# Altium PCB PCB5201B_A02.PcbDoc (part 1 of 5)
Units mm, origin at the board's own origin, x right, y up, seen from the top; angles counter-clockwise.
Board outline 115 x 60 mm, 6 copper layers (Top Layer, GND Layer 2, Signal Layer 3, Signal Layer 4, VCC Layer 5, Bottom Layer), stack 1.555 mm thick; 355 components, 250 nets, 1223 pads, 1070 vias.
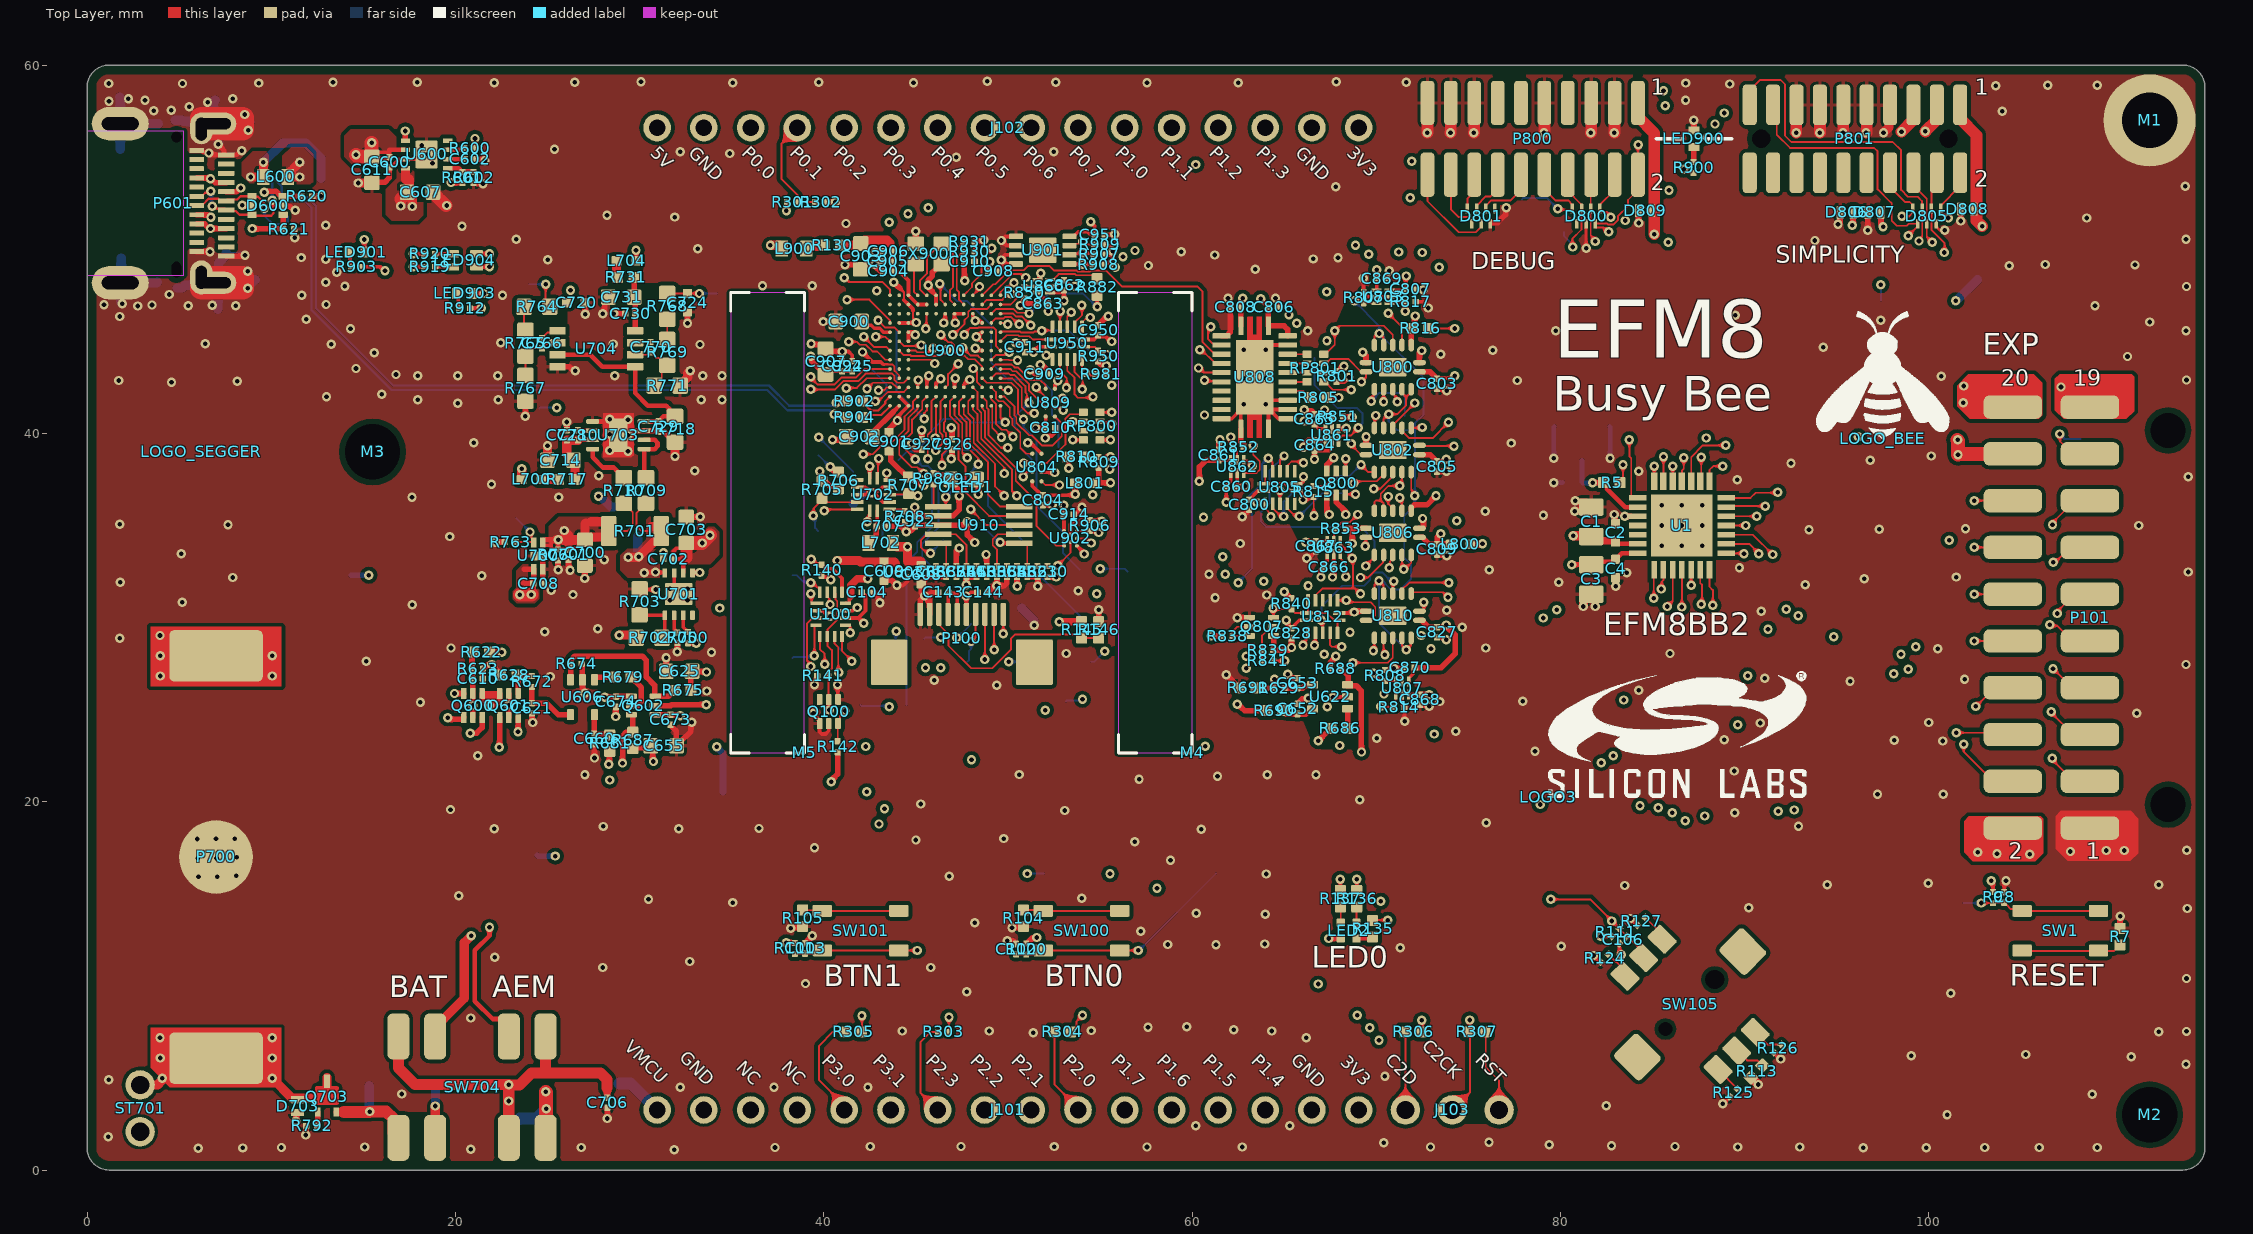
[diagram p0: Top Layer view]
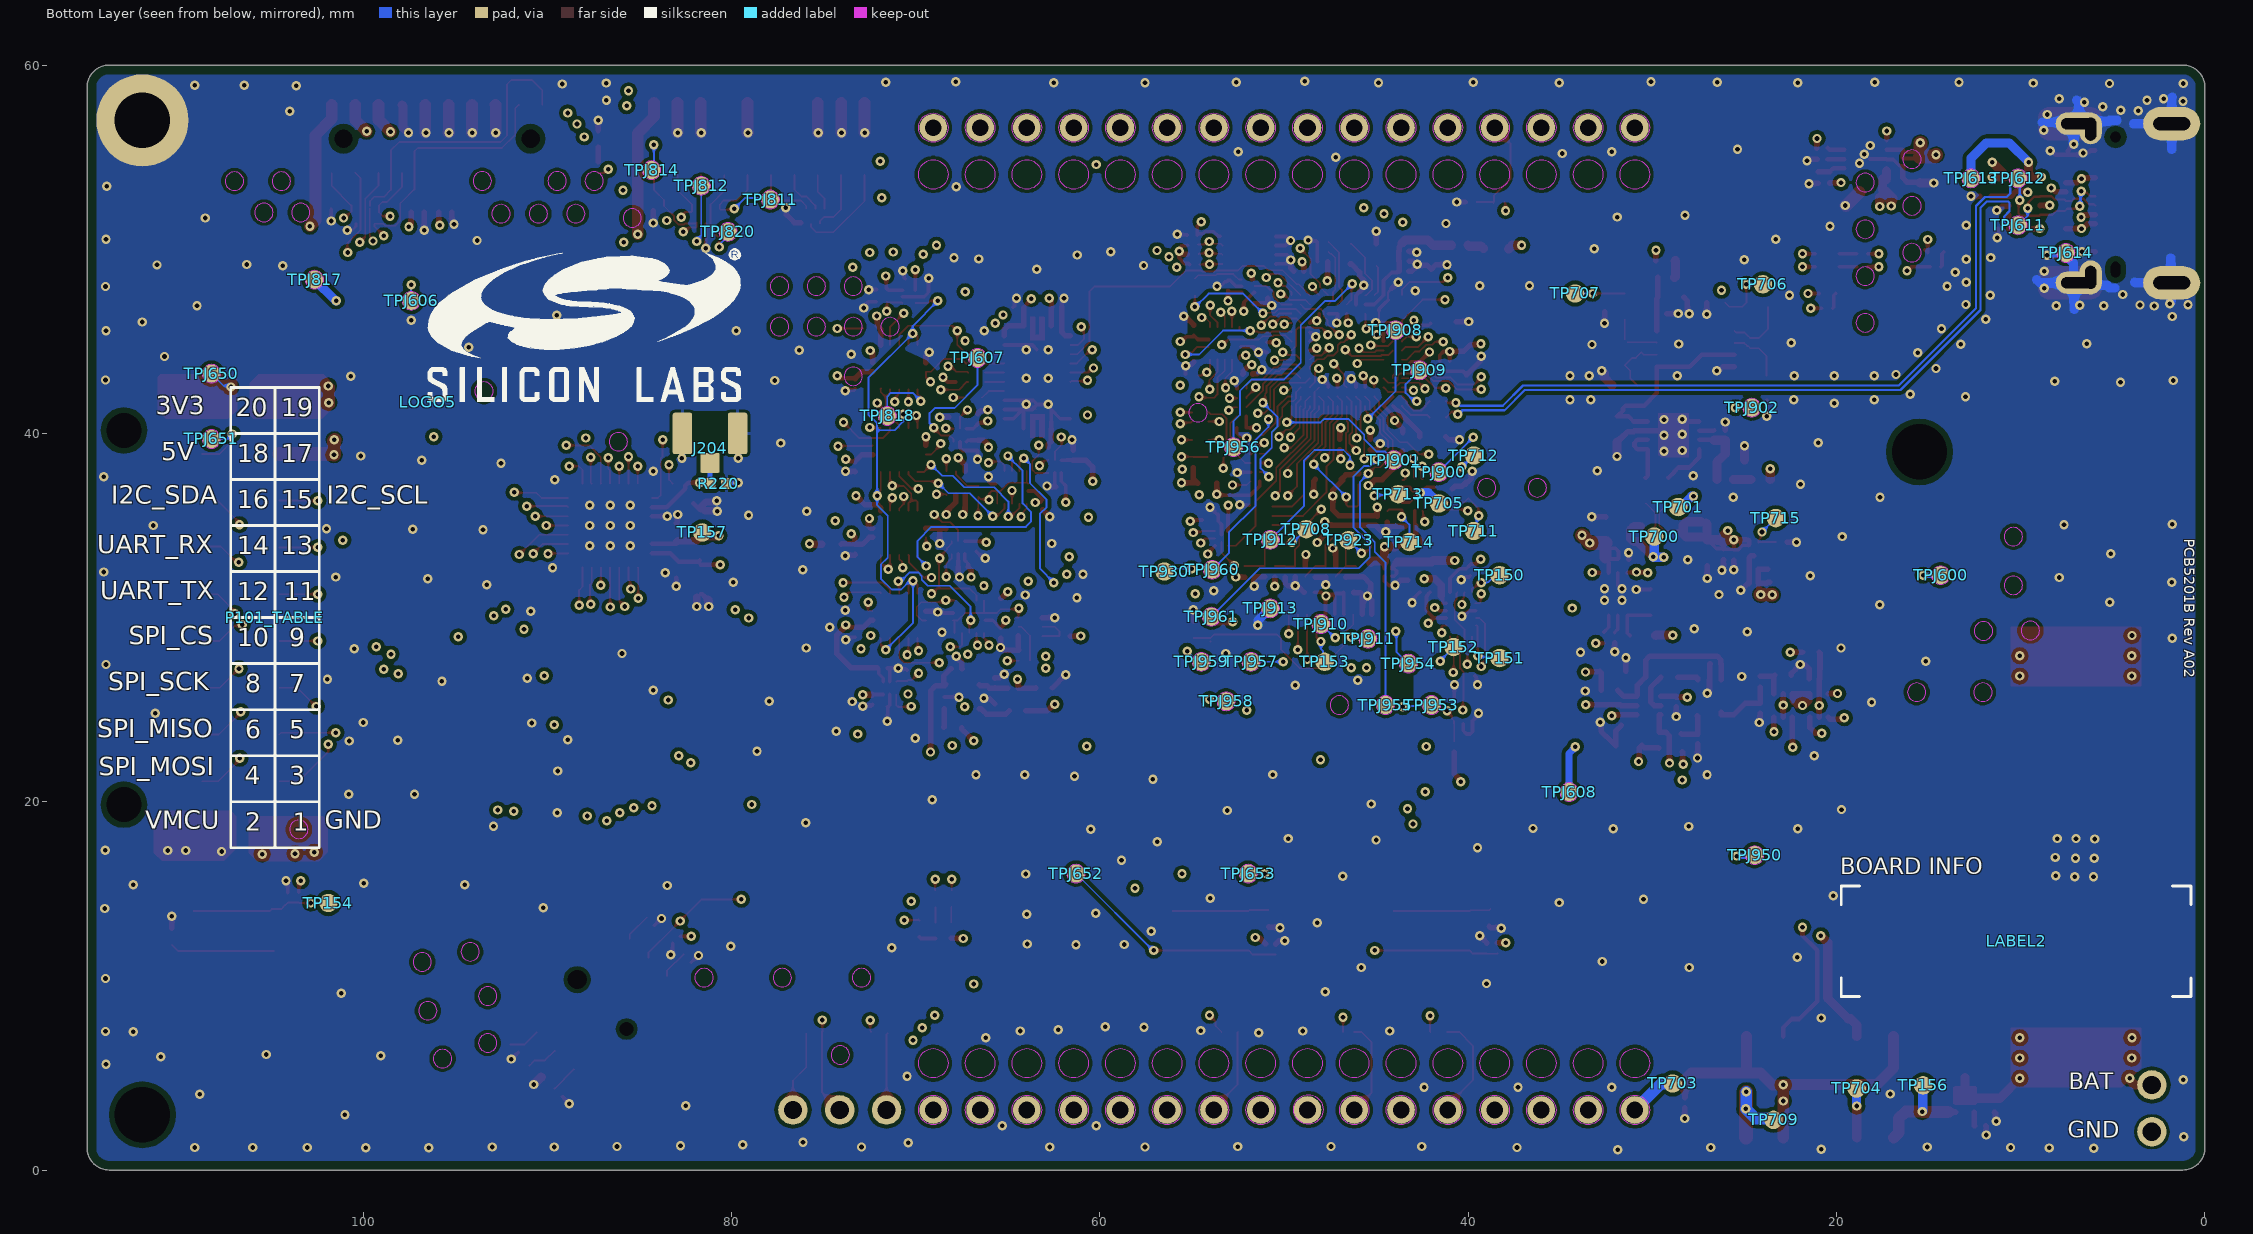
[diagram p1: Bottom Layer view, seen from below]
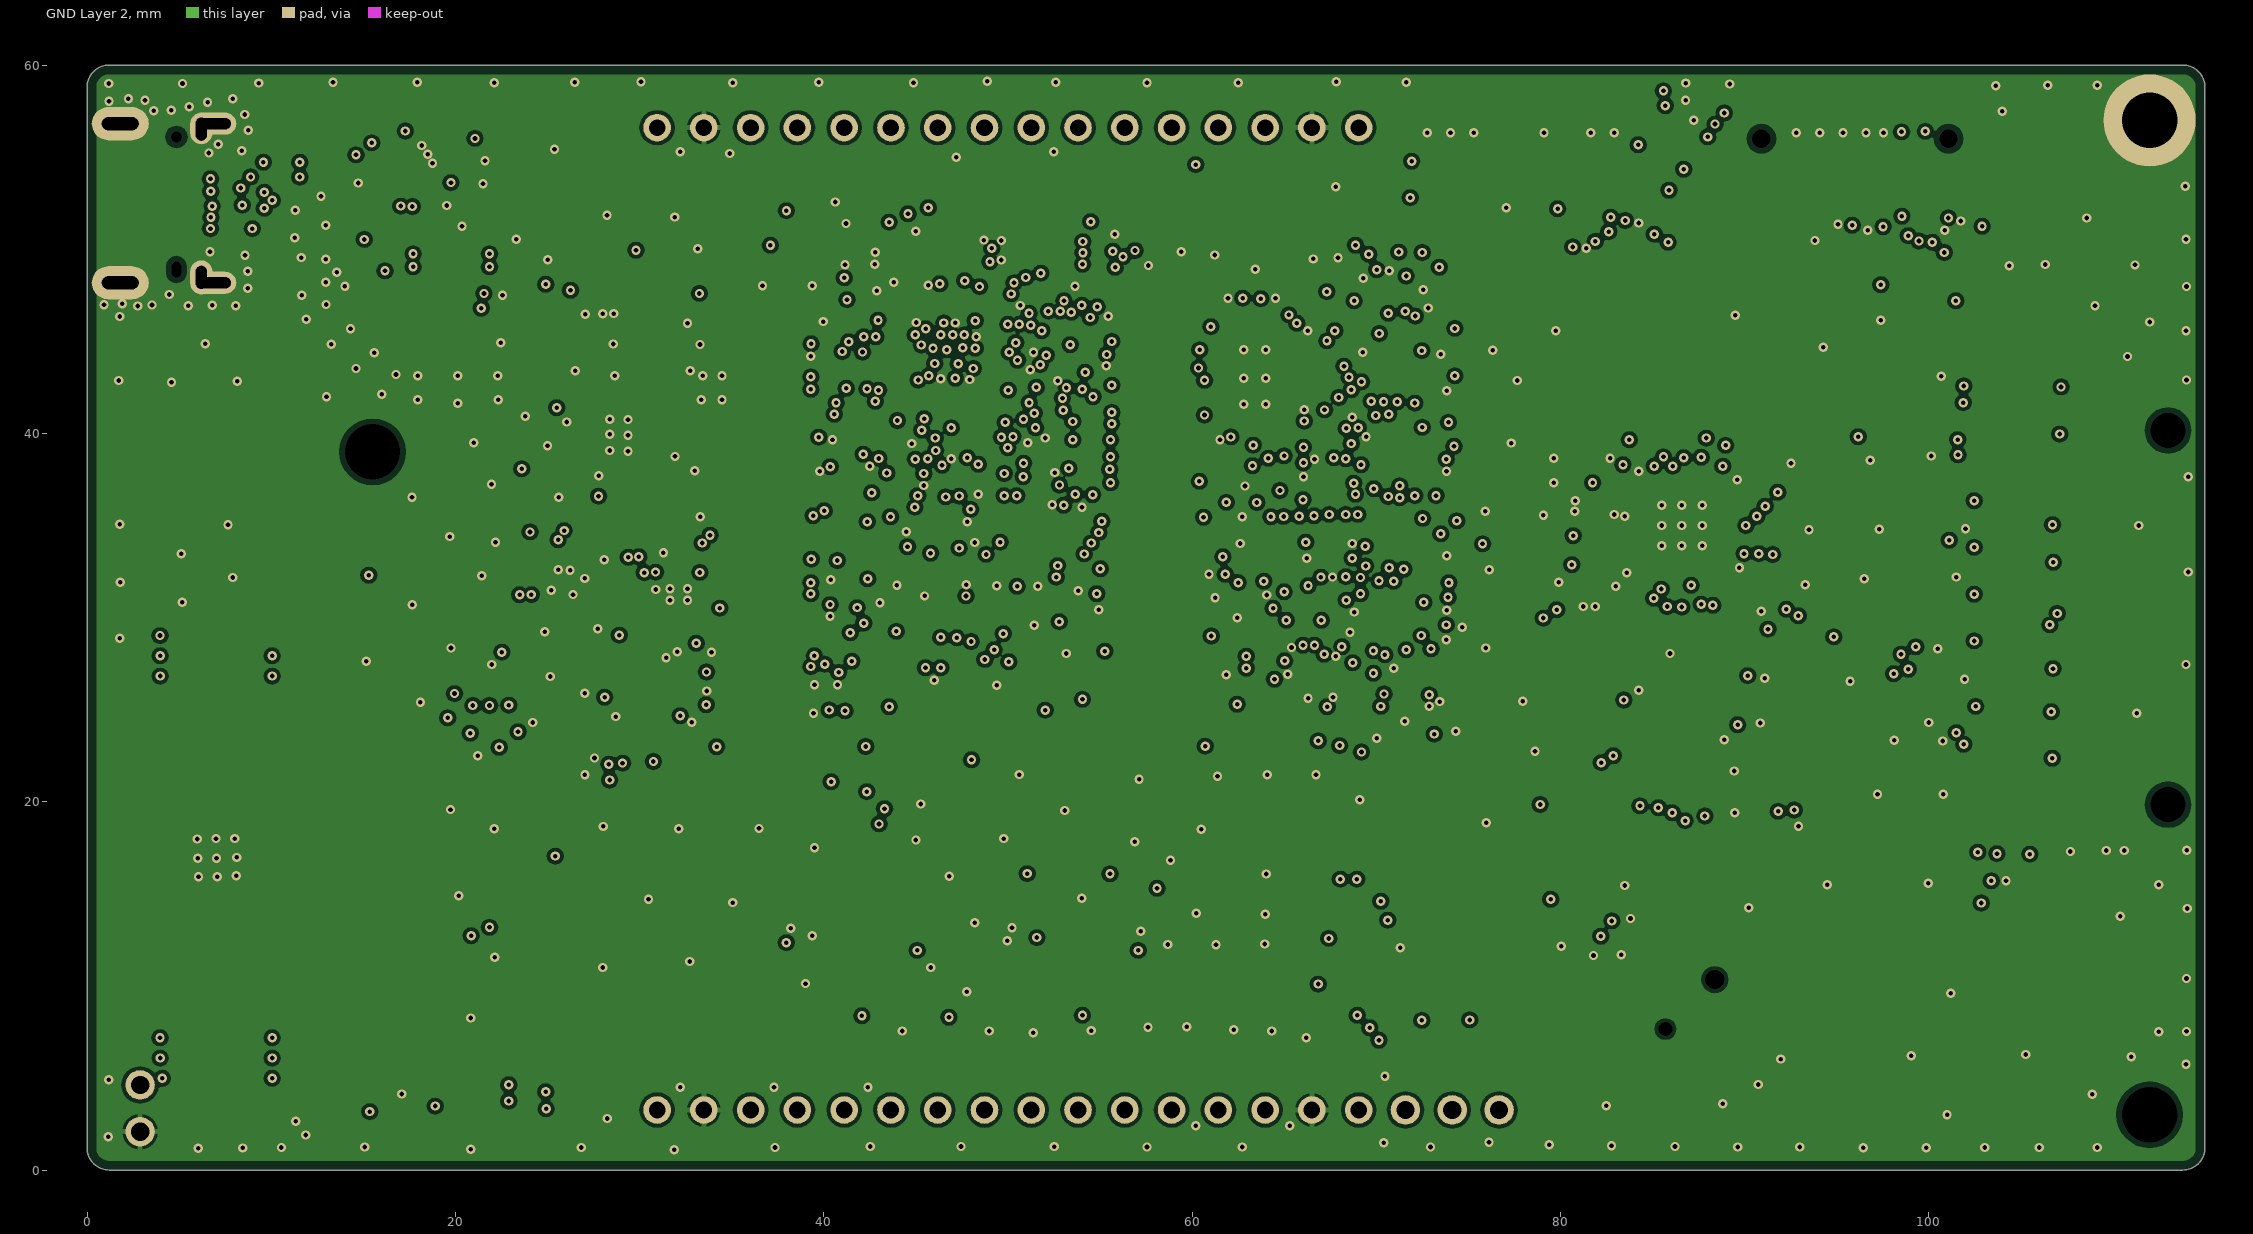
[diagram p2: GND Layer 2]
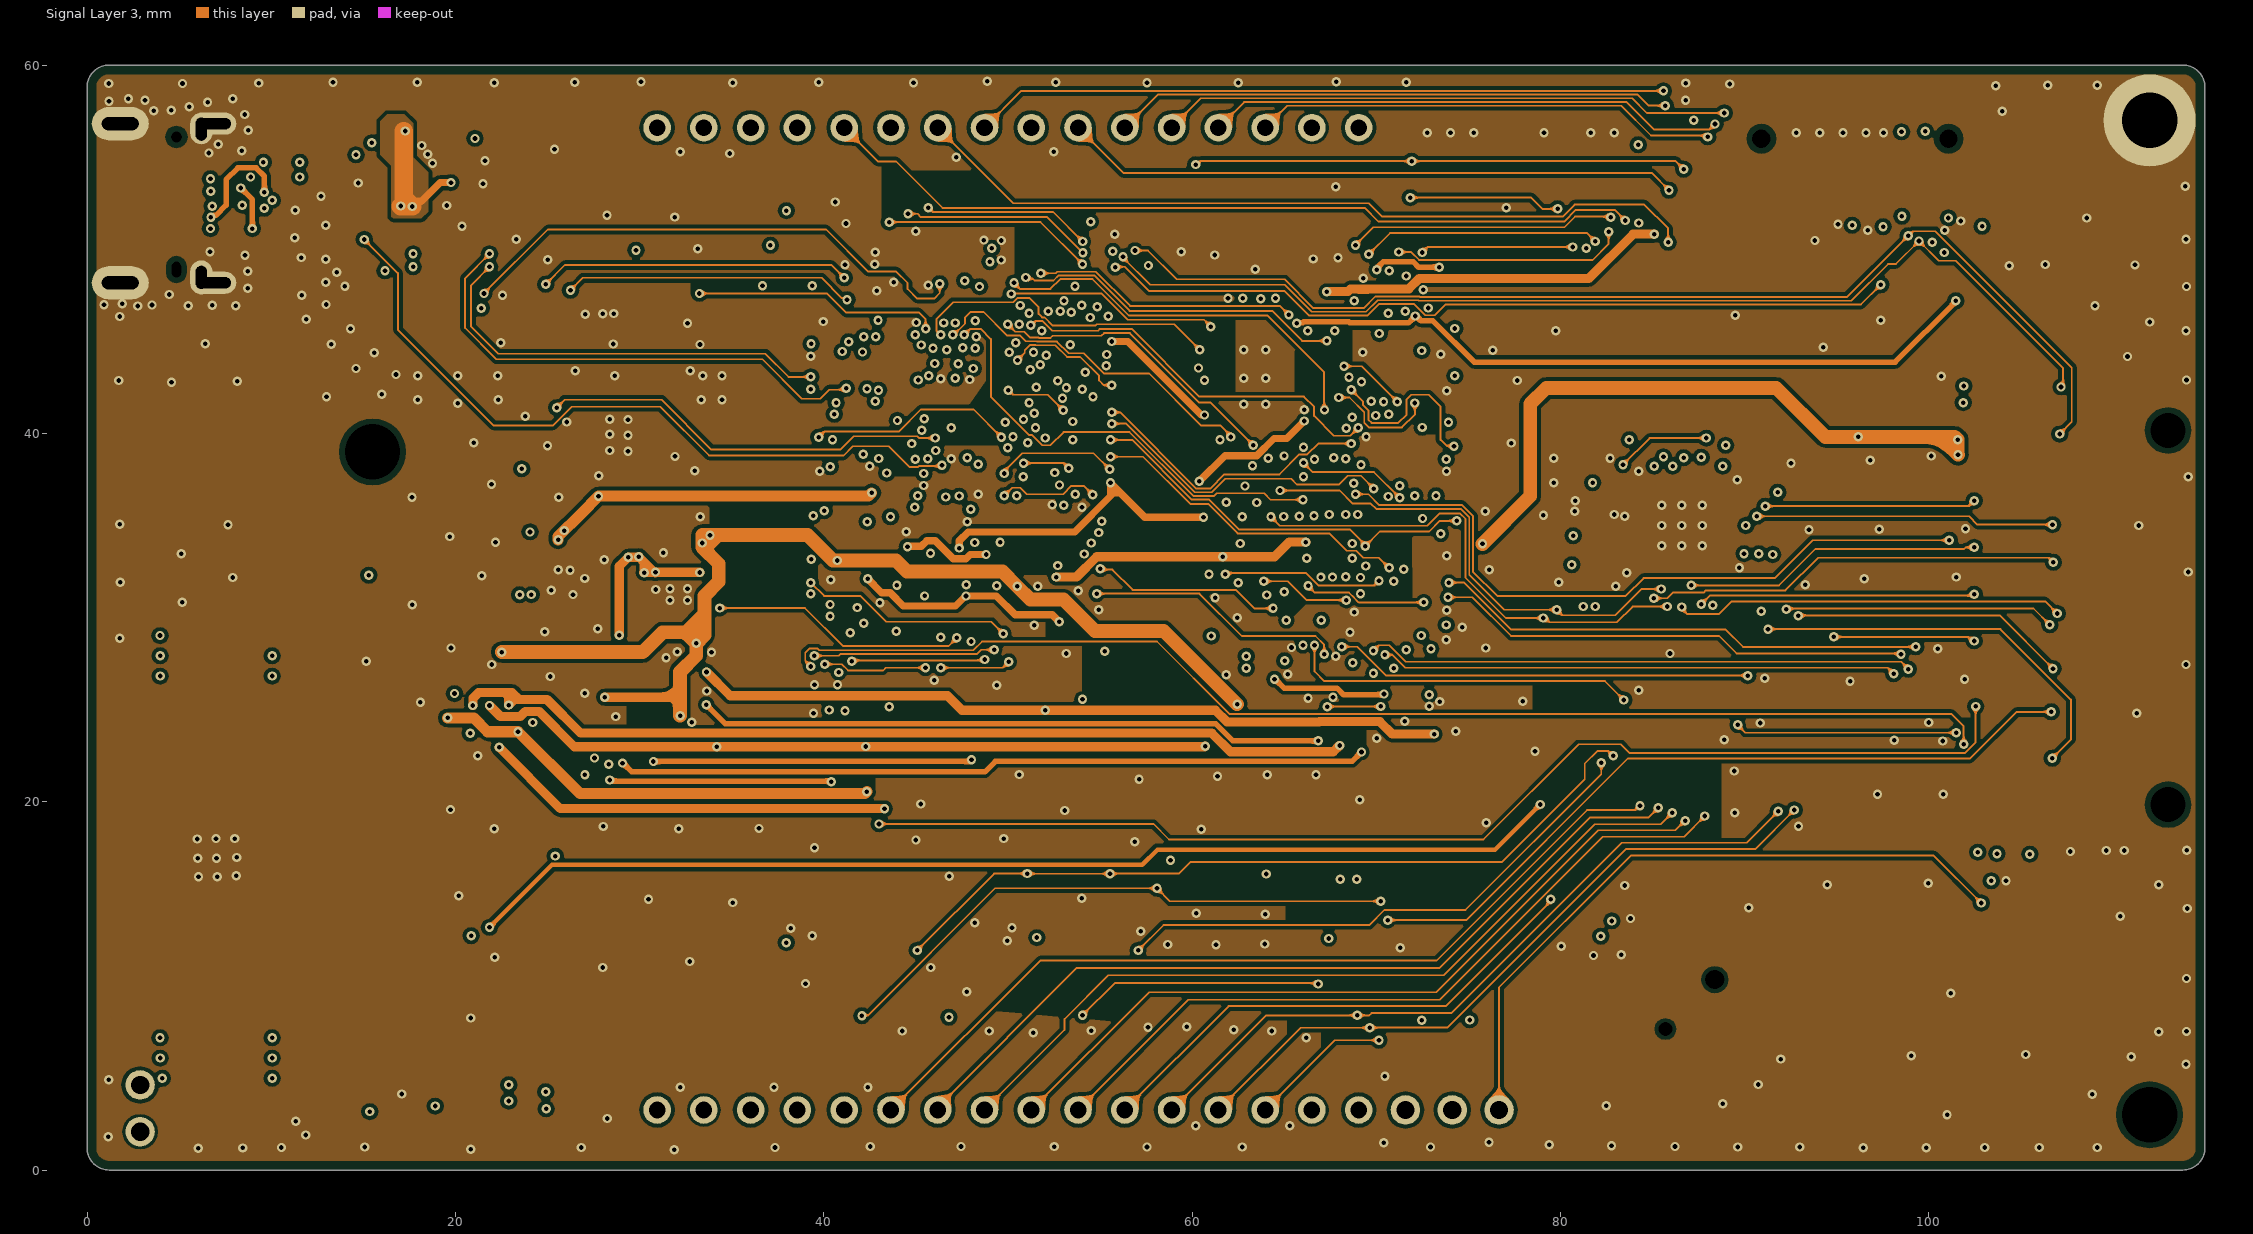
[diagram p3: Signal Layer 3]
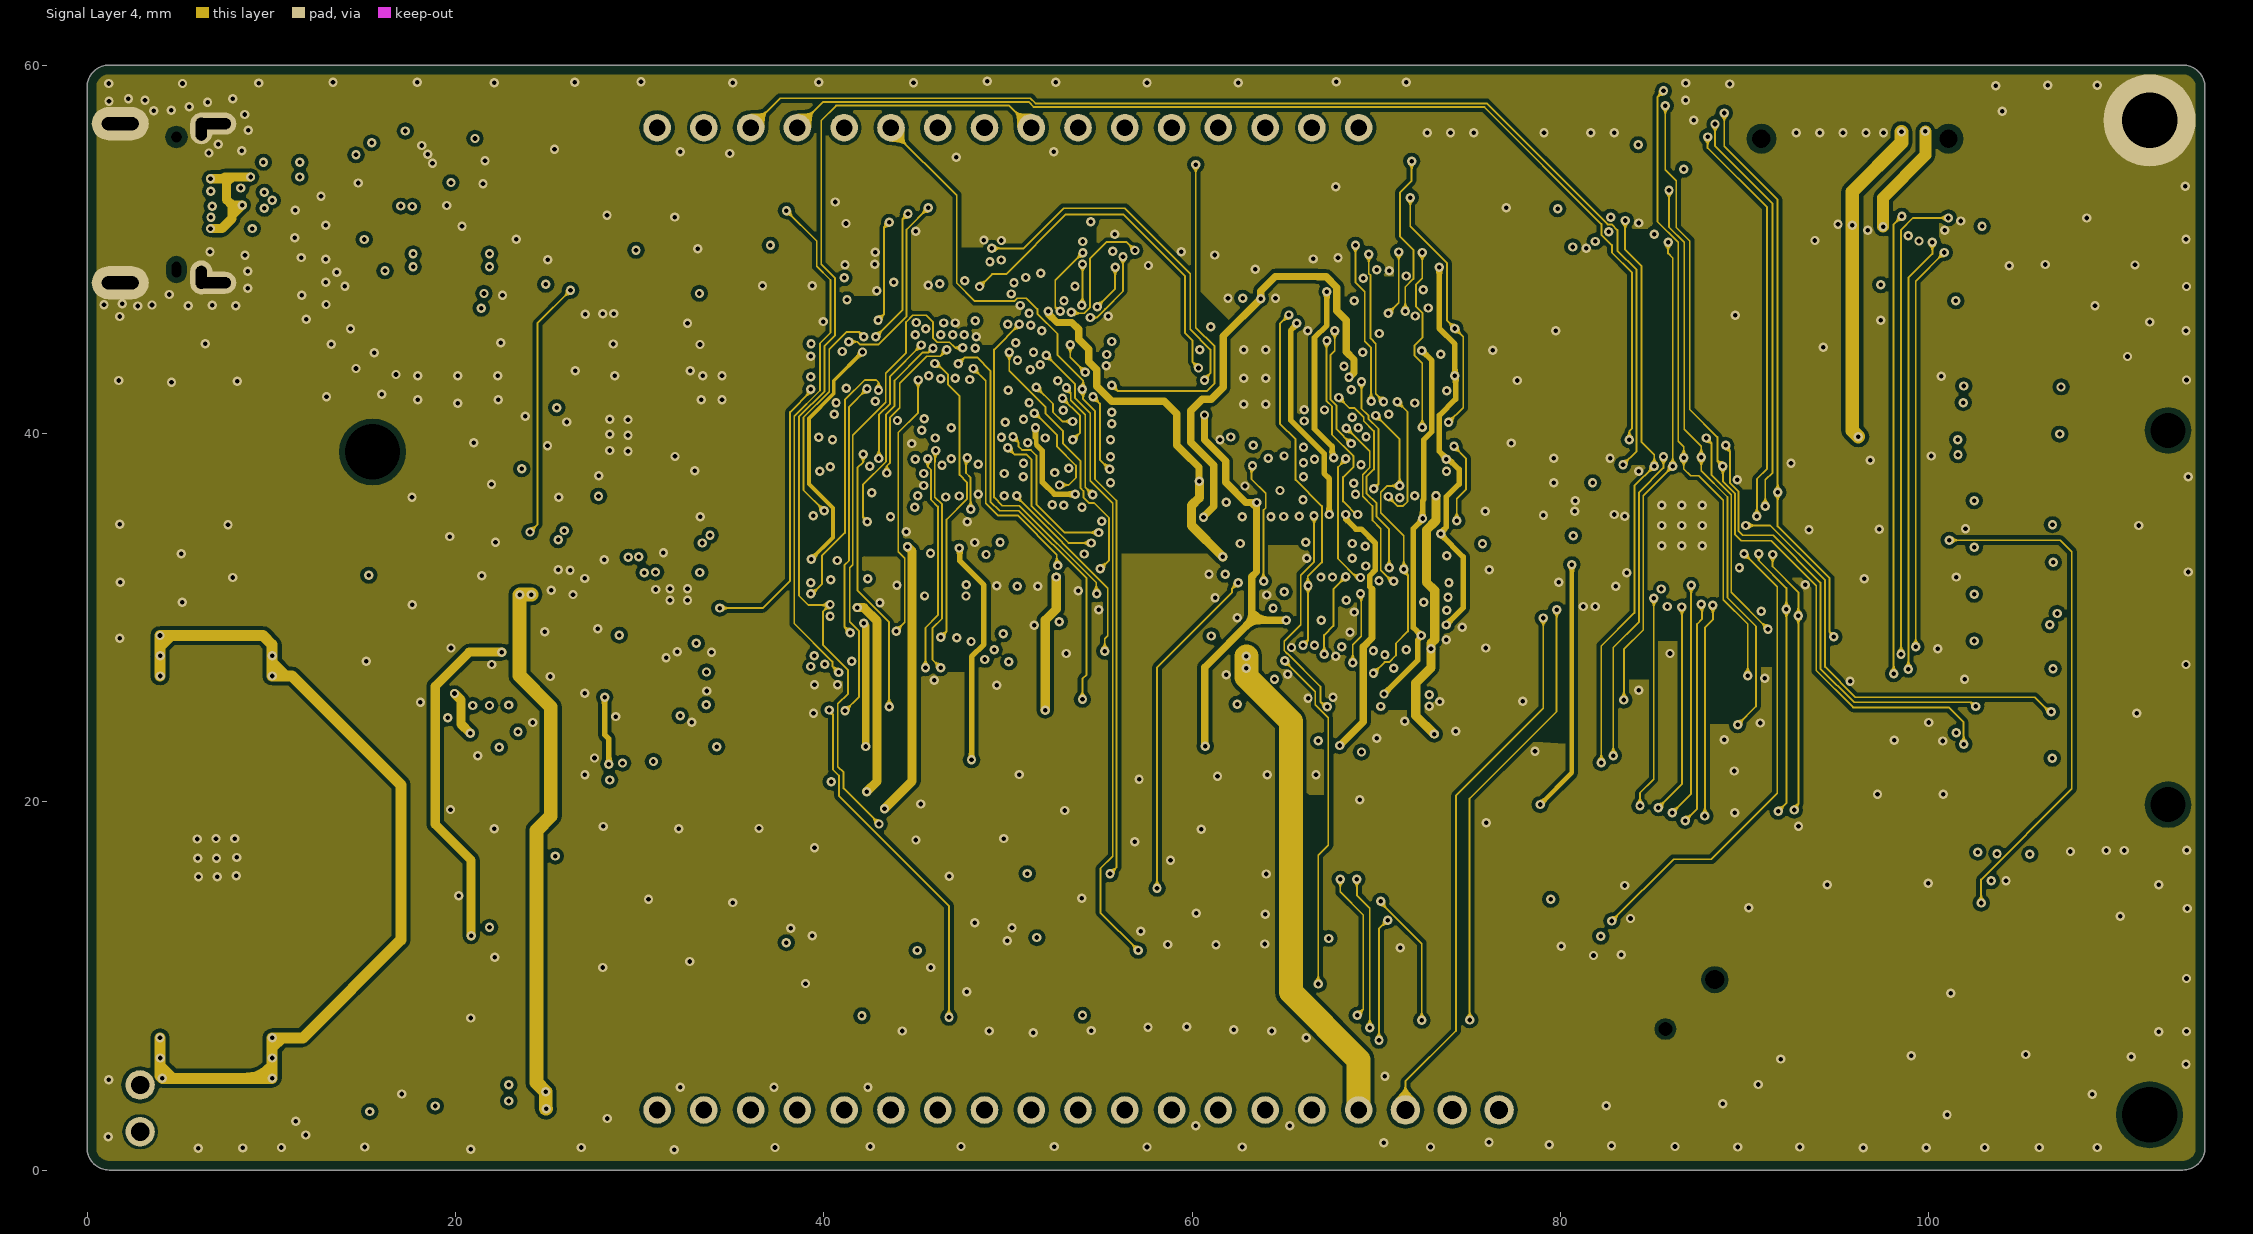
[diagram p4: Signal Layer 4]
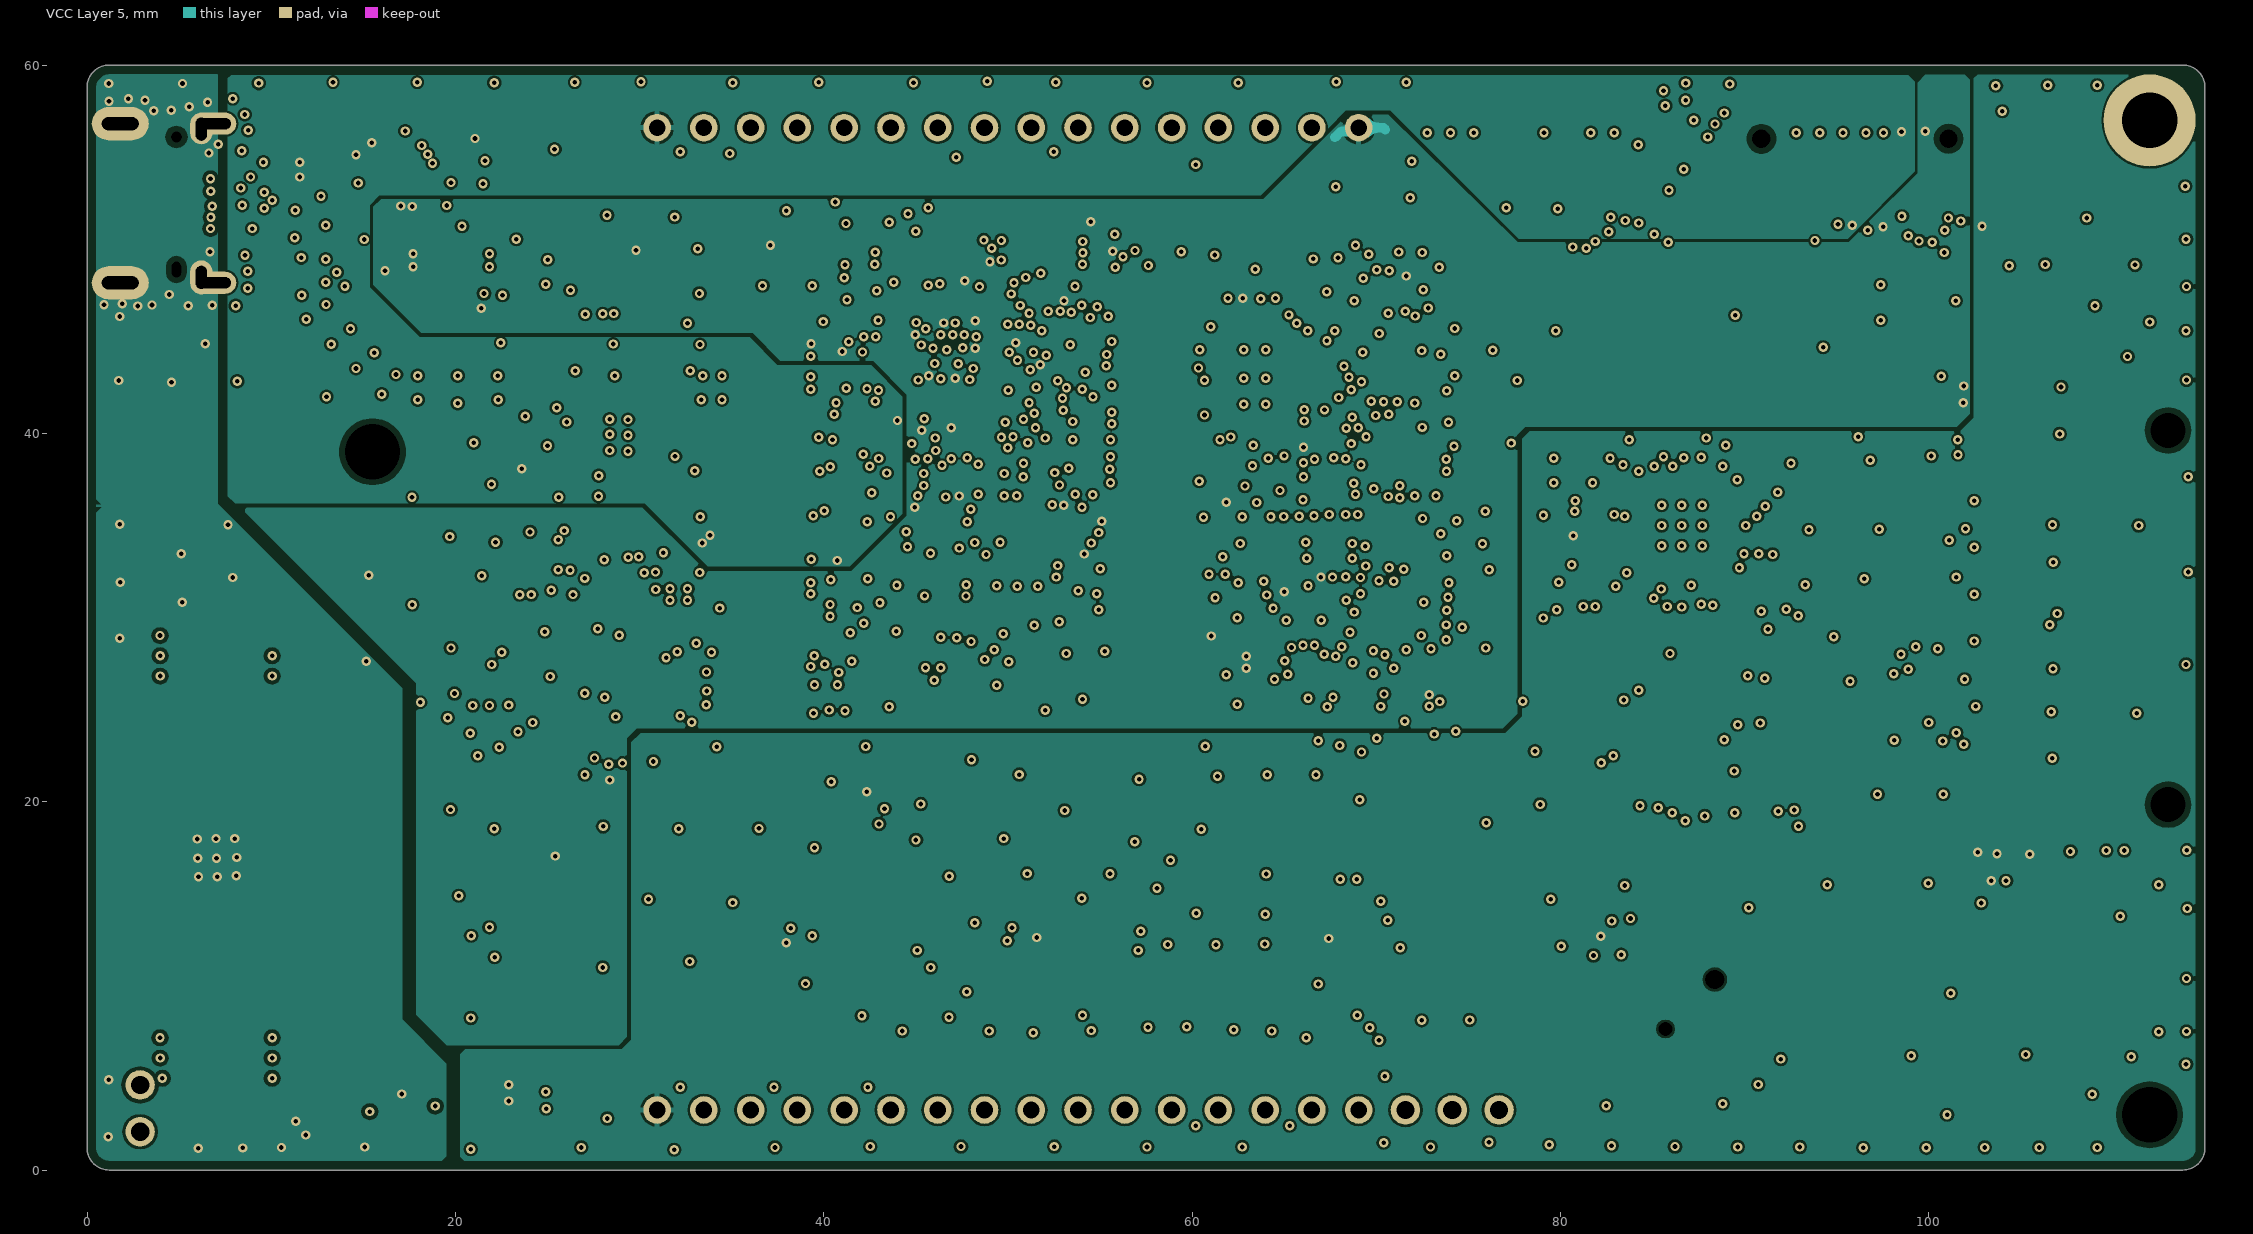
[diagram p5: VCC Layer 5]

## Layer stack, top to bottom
Top Solder: solder mask 0.03, Solder Resist, Dk 3.5
Top Layer: signal copper 0.035
Dielectric 1: prepreg 0.1, FR-4, Dk 4.2
GND Layer 2: signal copper 0.035
Dielectric 2: core 0.46, Core-009, Dk 4.2
Signal Layer 3: signal copper 0.035
Dielectric 3: prepreg 0.225, PP-006, Dk 4.2
Signal Layer 4: signal copper 0.035
Dielectric 4: core 0.46, Core-009, Dk 4.2
VCC Layer 5: signal copper 0.035
Dielectric  5: prepreg 0.1, FR-4, Dk 4.2
Bottom Layer: signal copper 0.035
Bottom Solder: solder mask 0.03, Solder Resist, Dk 3.5

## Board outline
0,1.2 0,58.8 cw(c1.2,58.8) 1.2,60 113.8,60 cw(c113.8,58.8) 115,58.8 115,1.2 cw(c113.8,1.2) 113.8,0 1.2,0 cw(c1.2,1.2)

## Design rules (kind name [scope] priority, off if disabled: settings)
BoardOutlineClearance BoardOutlineClearance_IGNORE_USB [HasFootprint('FCI_10137065_USB-C_RCPT_A1') or IsKeepOut] p1: gap=0.5 ignorepadtopadclearanceinfootprint=FALSE except(0: Region-OutlineEdge Region-CavityEdge Region-CutoutEdge Region-SplitBarrior Region-SplitContinuation; 0.25: THPad-OutlineEdge; 0.26: Arc-CutoutEdge Track-CutoutEdge SMDPad-CutoutEdge THPad-CutoutEdge Via-CutoutEdge Fill-CutoutEdge Poly-CutoutEdge Text-CutoutEdge)
BoardOutlineClearance [All] p2: gap=0.5 ignorepadtopadclearanceinfootprint=FALSE except(0.26: Arc-CutoutEdge Track-CutoutEdge SMDPad-CutoutEdge THPad-CutoutEdge Via-CutoutEdge Fill-CutoutEdge Poly-CutoutEdge Region-CutoutEdge Text-CutoutEdge; 0.4: THPad-OutlineEdge)
Clearance Clearance_NPL [(ObjectKind = 'Pad') And (Layer = 'MultiLayer') And (PadIsPlated = 'False')] p1: gap=0.3 ignorepadtopadclearanceinfootprint=FALSE
Clearance Clearance_Polygon_GND [InNet('GND') and InPolygon] p2: gap=0.2 ignorepadtopadclearanceinfootprint=FALSE
Clearance Clearance_Polygon_General [InPolygon] p3: gap=0.125 ignorepadtopadclearanceinfootprint=FALSE
Clearance Clearance_Via_Track [IsVia vs IsTrack] p4: gap=0.089 ignorepadtopadclearanceinfootprint=FALSE except(0: Arc-Hole Track-Hole SMDPad-Hole THPad-Hole Via-Hole Fill-Hole Poly-Hole Region-Hole Text-Hole)
Clearance [All] p5: gap=0.1 ignorepadtopadclearanceinfootprint=FALSE
Clearance Clearance_P601 [InComponent('P601')] p6: gap=0.1 ignorepadtopadclearanceinfootprint=FALSE
ComponentClearance ComponentClearance_IGNORE [HasFootprint('TESTJIGG_PCB4002_M14') OR HasFootprint('TAB50.5_T1.6_W2.4') OR HasFootprint('TP_6.0X6.0_MILLOUT_5.0X5.0_TH') Or InComponent('M1')] p1: gap=0 collisioncheckmode=3 verticalgap=0 showdistances=FALSE
ComponentClearance [All] p2: gap=0.2 collisioncheckmode=3 verticalgap=0.254 showdistances=FALSE
DiffPairsRouting DiffPairsRouting_90OHM [InDifferentialPair('USB_90') or InDifferentialPair('USB_90_U900')] p1: maxlimit=0.254 minlimit=0.12 mostfreqgap=0.254 toplayer_maxgap=0.12 toplayer_prefgap=0.12 toplayer_minwidth=0.12 toplayer_maxwidth=0.12 toplayer_prefwidth=0.12 bottomlayer_maxgap=0.12 bottomlayer_prefgap=0.12 bottomlayer_minwidth=0.12 bottomlayer_maxwidth=0.12 bottomlayer_prefwidth=0.12 impedanceprofiledriven=TRUE impedanceprofileid={B4300C99-598D-4438-91CE-854F904B181D} impedanceprofilevalue=90.000000 maxuncoupledlength=50
HoleSize [All] p1: absolutevalues=TRUE maxlimit=10 minlimit=0.1 maxpercent=80.000 minpercent=20.000
HoleToHoleClearance HoleToHoleClearance_general [Not InComponent('P601')] p1: gap=0.254 allowstackedmicrovias=TRUE
MinimumSolderMaskSliver MinimumSolderMaskSliver_IGNORE [InComponent('LOGO*') vs InComponent('LOGO*')] p1: minsoldermaskwidth=0
MinimumSolderMaskSliver [All] p2: minsoldermaskwidth=0.1
PolygonConnect PolygonConnect_Direct_Connect [InComponent('M1') or InComponent('J1') or InComponent('P700') or InComponent('P601')] p1: connectstyle=Direct reliefconductorwidth=0.33 reliefentries=4 polygonreliefangle="90 Angle" airgapwidth=0.152
PolygonConnect PolygonConnect_IGNORE_GND_FILL [IsThruPin vs InNet('GND') and not OnLayer('GND Layer 2')] p2: connectstyle=NoConnect reliefconductorwidth=0.3 reliefentries=4 polygonreliefangle="90 Angle" airgapwidth=0.15
PolygonConnect PolygonConnect_general [All] p3: thpad.connectstyle=Relief thpad.reliefconductorwidth=0.3 thpad.reliefentries=4 thpad.polygonreliefangle="90 Angle" thpad.airgapwidth=0.15 smdpad.connectstyle=Relief smdpad.reliefconductorwidth=0.2 smdpad.reliefentries=4 smdpad.polygonreliefangle="90 Angle" smdpad.airgapwidth=0.15 via.connectstyle=Direct via.reliefconductorwidth=0.33 via.reliefentries=4 via.polygonreliefangle="90 Angle" via.airgapwidth=0.127
RoutingVias RoutingVias_Through [InDrillLayerPair('Top Layer - Bottom Layer')] p1: holewidth=0.25 width=0.508 viastyle="Through Hole" minholewidth=0.25 minwidth=0.508 maxholewidth=1 maxwidth=1.5 useviatemplates=TRUE viatemplateguid#1={89E5EF08-91F7-4BC1-BF72-0CDB5ADAF91B} viatemplatename#1=v51h25m0mx0(Tol8-8)
ShortCircuit ShortCircuit_General [All] p1: allowed=FALSE
SilkToSilkClearance [All] p1: silktosilkclearance=0.102
SilkToSolderMaskClearance [IsPad] p1: minsilkscreentomaskgap=0.102 clearancetoexposedcopper=TRUE
SolderMaskExpansion [All] p1: expansion=0.05 istentingtop=FALSE
UnRoutedNet [All] p1: checkbadconnections=TRUE
Width [All] p1: maxlimit=5.08 minlimit=0.1 preferedwidth=0.1 minimp=50.000000 maximp=50.000000 favimp=50.000000
21 further rules are at their usual default settings.

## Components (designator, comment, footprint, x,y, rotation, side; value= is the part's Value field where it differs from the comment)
C1 "10U" C0805 81.675,35.2 r90 top
C2 "100N" C0402 83,34.6 r90 top
C3 "10U" C0805 81.675,32.069 r270 top
C4 "100N" C0402 83,32.662 r270 top
C8 "100N" C0201 104.1,14.8 r90 top
C102 "1N" C0201 50.45,12 r90 top
C103 "1N" C0201 38.986,12.031 r90 top
C104 "100N" C0201 42.348,31.374 r0 top
C106 "1N" C0201 83.4,12.5 r225 top
C143 "100N" C0201 46.499,31.364 r180 top
C144 "100N" C0201 48.625,31.368 r0 top
C600 "100N" C0201 16.417,54.726 r270 top
C602 "33N" C0201 20.782,54.897 r0 top
C607 "10U" C0603 18.082,53.097 r0 top
C608 "1U" C0402 45.3,32.325 r270 top
C609 "1U" C0402 43.275,32.525 r270 top
C610 "1N" C0201 21.2,26.675 r0 top
C611 "10U" C0603 15.465,54.314 r270 top
C621 "100N" C0201 24.15,25.075 r270 top
C625 "10U" C0603 32.148,27.08 r180 top
C632 "10N" C0201 51.05,32.5 r270 top
C635 "10N" C0201 49.4,32.5 r270 top
C638 "10N" C0201 46.1,32.5 r270 top
C641 "10N" C0201 47.75,32.5 r270 top
C652 "100N" C0201 65.725,25.036 r90 top
C653 "100N" C0201 65.72,26.44 r90 top
C655 "10U" C0603 31.304,23.036 r0 top
C660 "100N" C0201 27.537,23.41 r270 top
C673 "100N" C0201 31.675,24.45 r270 top
C674 "100N" C0201 28.713,25.422 r270 top
C700 "10U" C0603 27.033,33.525 r270 top
C701 "100N" C0201 26.134,33.412 r270 top
C702 "100N" C0201 31.57,33.171 r180 top
C703 "10U" C0603 32.535,34.761 r90 top
C705 "33N" C0201 32.05,28.904 r270 top
C706 "100N" C0201 28.25,3.65 r270 top
C707 "100N" C0201 43.15,34.95 r0 top
C708 "100N" C0201 24.5,31.85 r0 top
C710 "100N" C0201 26.65,39.9 r90 top
C714 "10U" C0603 25.7,38.55 r180 top
C720 "1N" C0402 26.55,47.1 r0 top
C724 "1N" C0402 32.6,47.1 r270 top
C728 "100N" C0201 26.05,39.9 r90 top
C729 "2N2" C0201 31.025,40.375 r270 top
C730 "100N" C0201 29.497,46.509 r180 top
C731 "10U" C0603 29,47.4 r180 top
C766 "10P" C0201 24.7,44.9 r90 top
C770 "10P" C0201 30.6,44.675 r90 top
C800 "100N" C0201 63.1,36.125 r270 top
C803 "100N" C0201 73.3,42.7 r270 top
C804 "100N" C0201 51.9,36.375 r270 top
C805 "100N" C0201 73.3,38.2 r270 top
C806 "100N" C0201 64.45,46.85 r0 top
C807 "100N" C0201 71.85,47.825 r0 top
C808 "100N" C0201 62.35,46.85 r180 top
C809 "100N" C0201 73.3,33.7 r270 top
C810 "100N" C0201 52.3,40.3 r0 top
C827 "100N" C0201 73.3,29.2 r270 top
C828 "100N" C0201 65.4,29.15 r270 top
C860 "100N" C0201 62.125,37.1 r0 top
C861 "100N" C0201 61.45,38.825 r90 top
C862 "100N" C0201 53.05,48.05 r90 top
C863 "100N" C0201 51.9,47.05 r180 top
C864 "100N" C0201 66.65,39.35 r270 top
C865 "100N" C0201 66.65,40.775 r90 top
C866 "100N" C0201 67.425,32.725 r0 top
C867 "100N" C0201 66.725,33.875 r270 top
C868 "100N" C0201 72.376,25.539 r270 top
C869 "100N" C0201 70.294,48.403 r0 top
C870 "100N" C0201 71.814,27.284 r180 top
C900 "1U" C0603 41.35,46.075 r180 top
C901 "1U" C0402 43.55,39.55 r270 top
C902 "4U7" C0603 41.925,39.825 r180 top
C903 "10U" C0603 42.006,49.615 r270 top
C904 "10N" C0201 43.498,48.802 r180 top
C905 "10N" C0201 43.485,49.352 r180 top
C906 "10N" C0201 43.498,49.896 r180 top
C907 "4U7" C0603 40.1,43.9 r270 top
C908 "100N" C0201 49.2,48.8 r0 top
C909 "100N" C0201 51.98,43.224 r180 top
C910 "100N" C0201 47.909,49.333 r0 top
C911 "100N" C0201 50.925,44.675 r270 top
C914 "100N" C0201 53.3,35.6 r0 top
C921 "4U7" C0603 47.6,37.5 r0 top
C922 "100N" C0201 44.95,35.225 r270 top
C924 "100N" C0201 41,43.65 r270 top
C925 "100N" C0201 41.55,43.65 r270 top
C926 "100N" C0201 46.975,39.4 r270 top
C927 "100N" C0201 45.325,39.4 r270 top
C950 "10N" C0201 54.9,45.6 r90 top
C951 "100N" C0201 54.997,50.778 r0 top
D600 "DT1446-04" SOT563_DIODES 9.797,52.374 r180 top
D703 "ESD" X2-DFN1006-2 11.425,3.475 r270 top
D800 "PUSB3AB6" DFN2111-7_M050_1.2X2.1_NXP 81.4,51.8 r270 top
D801 "PUSB3AB6" DFN2111-7_M050_1.2X2.1_NXP 75.7,51.8 r270 top
D805 "PUSB3AB6" DFN2111-7_M050_1.2X2.1_NXP 99.9,51.8 r270 top
D806 "ESD" X2-DFN1006-2 95.55,52 r180 top
D807 "ESD" X2-DFN1006-2 97.05,52 r180 top
D808 "ESD" X2-DFN1006-2 102.098,52.181 r180 top
D809 "ESD" X2-DFN1006-2 84.6,52.1 r180 top
J101 "1X16 2.54MM" HDR_M254-1X16_NO_3D 30.95,3.262 r0 top locked
J102 "1X16 2.54MM" HDR_M254-1X16_NO_3D 30.95,56.602 r0 top locked
J103 "1X3 2.54MM" HDR_M254-1X3_NO_3D 71.59,3.262 r0 top
J204 "U.FL" HRS_U.FL-R-SMT 81.175,40 r180 bottom
L600 "742792662" COIL_WURTH_CBF_0603 10.235,53.926 r0 top
L700 "742792796" COIL_0402 24.125,37.5 r0 top
L702 "74279266" COIL_WURTH_CBF_0603 43.1,34.05 r180 top
L704 "742792796" COIL_0402 29.282,49.375 r180 top
L800 "742792796" COIL_0402 74.574,33.978 r180 top
L801 "742792796" COIL_0402 54.175,37.3 r180 top
L900 "74279266" COIL_WURTH_CBF_0603 38.39,50.035 r0 top
LABEL2 "Comment" LABEL_4CORNERS_19.0X6.0 10.25,12.425 r180 bottom
LED2 "RGB" LED_LUMEX_SML-LX0404-4 68.5,13 r0 top
LED900 "YELLOW" LED_0402_CAT2 87.25,56 r90 top
LED901 "BLUE" LED_0402_CAT2 14.625,49.85 r0 top
LED903 "RED" LED_0402 20.5,47.6 r180 top
LED904 "LED_G_R" LED_AVAGO_HSMF-C165-4 20.5,49.4 r0 top
LOGO3 "Comment" LOGO_SILABS_W14.0_SILK 79.35,20.25 r0 top
LOGO5 "Comment" LOGO_SILABS_W18.0 96.5,41.7 r180 bottom
LOGO_BEE "Comment" LOGO_BEE_H7.0 97.5,39.7 r0 top
LOGO_SEGGER "Comment" LOGO_SEGGER_10.0X5.0_SM 6.2,39 r0 top
M1 "HOLE_PTH_3MM" HOLE_3.0_5.0_PL 112,57 r0 top
M2 "Comment" HOLE_3.0_NPL 112,3 r0 top
M3 "Comment" HOLE_3.0_NPL 15.5,39 r90 top
M4 "Comment" ADHESIVE_PAD_25.0X4.0 60,22.65 r90 top
M5 "Comment" ADHESIVE_PAD_25.0X4.0 38.95,22.65 r90 top
OLED1 "Comment" OLED_LS013B7DH03 47.725,37.075 r0 top
P100 "L-KLS1-242D-1.2-10" KLS_KLS1-242D_FPC_0.5-10 45.25,30.175 r0 top
P101 "HEADER_2X10_2.54MM_TH" WCON_1125B-1210_HOR_PEG-2X10 113,19.84 r90 top
P101_TABLE "Comment" LABEL_P101_PIN_TABLE_SL 104.8,30 r180 bottom
P601 "AMPH_10137065" FCI_10137065_USB-C_RCPT_A1 4.85,52.5 r270 top
P700 "CR2032" BAT_HOLD_MPD_BK-912_CR2032 7,17 r270 top
P800 "HEADER_DEBUG_ETM" WCON_3132_HDR_M127_SMD-2X10 78.5,56 r180 top
P801 "HEADER_2X10_1.27MM_SMD" HDR_SULLINS_M127_PEG-2X10 101.08,56 r180 top
Q100 "DMN5L06VK" SOT563 40.275,24.89 r270 top
Q600 "BSS84" SOT563 20.95,25.225 r90 top
Q601 "DMN5L06VK" SOT563 22.9,25.225 r90 top
Q602 "BSS84" SOT563 30.2,25.225 r0 top
Q703 "DMG3415" X2-DFN2015-3_DIODES 13.025,4.05 r90 top
Q800 "DMN5L06VK" SOT563 67.825,37.3 r270 top
Q807 "DMN5L06VK" SOT563 63.775,29.5 r180 top
R5 "0R" R0402 82.8,37.325 r0 top
R7 "100R" R0402 110.4,12.675 r270 top
R9 "1K" R0201 103.5,14.8 r270 top
R100 "1M" R0201 51,12 r90 top
R101 "1M" R0201 38.429,12.033 r90 top
R104 "100R" R0402 50.847,13.67 r270 top
R105 "100R" R0402 38.85,13.675 r270 top
R111 "10K" R0201 83,12.9 r225 top
R113 "100R" R0402 90.66,5.355 r45 top
R124 "15K" R0201 82.4,11.5 r45 top
R125 "10K" R0201 89.4,4.2 r45 top
R126 "33K" R0201 91.8,6.6 r45 top
R127 "60K4" R0201 84.4,13.5 r45 top
R130 "1R" R0402 40.454,50.219 r0 top
R135 "698R" R0402 69.8,13.1 r90 top
R136 "910R" R0402 68.944,14.734 r90 top
R137 "2K32" R0402 68.052,14.737 r90 top
R140 "100K" R0201 39.888,32.575 r90 top
R141 "10M" R0201 39.942,26.832 r0 top
R142 "100K" R0201 40.756,22.983 r270 top
R145 "0R" R0402 54.007,29.332 r90 top
R146 "0R" R0402 54.932,29.332 r270 top
R220 "49R9" R0402 80.725,37.275 r0 bottom
R301 "0R" R0201 38.3,52.564 r0 top
R302 "0R" R0201 39.846,52.564 r180 top
R303 "0R" R0201 46.5,7.5 r180 top
R304 "0R" R0402 52.95,7.5 r180 top
R305 "1K" R0402 41.6,7.5 r180 top
R306 "1K" R0402 72,7.5 r180 top
R307 "1K" R0402 75.47,7.5 r180 top
R600 "10K" R0201 20.782,55.497 r0 top
R601 "180K" R0201 20.382,53.897 r270 top
R602 "110K" R0201 20.982,53.897 r90 top
R620 "5K1" R0201 11.924,52.88 r180 top
R621 "5K1" R0201 10.95,51.1 r180 top
R622 "47R" R0402 21.4,28.125 r0 top
R623 "10K" R0201 21.2,27.225 r180 top
R628 "1M" R0402 22.9,26.875 r180 top
R629 "1K" R0201 64.719,26.163 r180 top
R630 "4K7" R0201 52.15,32.5 r270 top
R631 "10K" R0201 51.6,32.5 r90 top
R633 "47K" R0201 50.5,32.5 r270 top
R634 "47K" R0201 49.95,32.5 r90 top
R636 "47K" R0201 47.2,32.5 r90 top
R637 "47K" R0201 46.65,32.5 r90 top
R639 "47K" R0201 48.85,32.5 r90 top
R640 "47K" R0201 48.3,32.5 r90 top
R672 "1K" R0201 24.15,26.525 r90 top
R674 "4K7" R0201 26.56,27.49 r0 top
R675 "3R3" R0402 32.332,26.05 r0 top
R679 "0R" R0402 29.085,26.761 r0 top
R681 "33R" R0402 28.38,23.172 r270 top
R686 "0R" R0402 68.008,23.984 r180 top
R687 "3R3" R0402 29.629,23.333 r270 top
R688 "4K7" R0201 67.786,27.233 r180 top
R690 "33R" R0402 64.471,24.944 r180 top
R691 "1M" R0402 63.027,26.187 r180 top
R700 "10K" R0201 32.627,28.911 r270 top
R701 "4R7" R1206 29.75,34.7 r180 top
R702 "180K" R0603 30.516,28.9 r180 top
R703 "110K" R0603 30,30.856 r270 top
R705 "267R" R0402 39.9,36.929 r270 top
R706 "10K2" R0402 40.8,37.444 r90 top
R707 "24K9" R0402 44.6,37.189 r270 top
R708 "1M" R0201 44.4,35.475 r90 top
R709 "1K8" R0603 30.35,36.9 r270 top
R710 "1K8" R0603 29.15,36.9 r270 top
R717 "10R" R0402 26.05,37.5 r0 top
R718 "12K" R0603 31.925,40.225 r90 top
R731 "1R" R0402 29.25,48.475 r180 top
R760 "330K" R0201 25.573,33.403 r90 top
R763 "100K" R0201 22.979,34.098 r0 top
R764 "90R9" R0603 24.425,46.875 r0 top
R765 "51K" R0603 23.8,44.9 r90 top
R767 "160R" R0603 23.8,42.45 r90 top
R768 "90R9" R0603 31.5,46.9 r90 top
R769 "51K" R0603 31.5,44.4 r90 top
R771 "51K" R0603 31.5,42.6 r180 top
R792 "1K" R0201 12.2,2.4 r0 top
R801 "47K" R0201 67.849,43.093 r270 top
R805 "33R" R0402 66.85,41.95 r0 top
R807 "100K" R0201 69.325,47.375 r90 top
R808 "100K" R0201 70.475,26.85 r90 top
R809 "100K" R0201 54.925,38.425 r270 top
R810 "33R" R0402 53.7,38.725 r0 top
R814 "100K" R0201 71.232,25.13 r180 top
R815 "1K" R0201 66.59,36.842 r270 top
R816 "100K" R0402 72.4,45.7 r180 top
R817 "100K" R0201 71.85,47.15 r180 top
R838 "100K" R0201 61.901,28.996 r180 top
R839 "10M" R0201 64.1,28.225 r180 top
R840 "100K" R0201 65.4,30.75 r90 top
R841 "1K" R0201 64.104,27.652 r0 top
R850 "100K" R0201 50.9,47.642 r90 top
R851 "100K" R0201 67.9,40.912 r180 top
R852 "100K" R0201 62.5,39.25 r180 top
R853 "100K" R0201 68.075,34.825 r180 top
R882 "220R" R0402 54.85,47.95 r270 top
R900 "2K05" R0201 87.235,54.44 r90 top
R902 "33R" R0402 41.65,41.75 r0 top
R903 "5K76" R0201 14.625,49.05 r180 top
R904 "33R" R0402 41.65,40.875 r0 top
R906 "10K" R0201 54.45,35 r90 top
R907 "4K7" R0201 54.965,49.726 r180 top
R908 "4K7" R0201 54.898,49.168 r180 top
R909 "10K" R0201 54.976,50.251 r180 top
R912 "2K15" R0201 20.5,46.8 r180 top
R919 "1K" R0201 18.6,49.05 r0 top
R920 "2K37" R0201 18.6,49.75 r0 top
R930 "1K" R0201 47.902,49.863 r0 top
R931 "1K" R0201 47.9,50.4 r0 top
R950 "100K" R0201 54.9,44.2 r270 top
R981 "100K" R0201 55.05,43.225 r0 top
R982 "10K" R0201 45.954,37.531 r270 top
RP800 "33R" RES_MNR04-8 54.55,40.4 r90 top
RP801 "33R" RES_MNR04-8 66.7,43.55 r90 top
ST701 "2X1 2.54MM" HDR_M254-1X2 2.875,2.08 r90 top
SW1 "PTS810" SW_CK_PTS810_SJM_250 107.15,13 r0 top
SW100 "PTS810" SW_CK_PTS810_SJM_250 54,13 r0 top
SW101 "PTS810" SW_CK_PTS810_SJM_250 42,13 r0 top
SW105 "ALPS_SKRH_4" SW_ALPS_SKRHAAE010 87.05,9 r135 top
SW704 "SW_DP3T_0" CK_DP3T_JS203011SCQN 20.9,4.5 r0 top
TP150 "TP_SMD" TP_1.0_SMD 38.3,32.3 r270 bottom
TP151 "TP_SMD" TP_1.0_SMD 38.3,27.8 r0 bottom
TP152 "TP_SMD" TP_1.0_SMD 40.8,28.4 r270 bottom
TP153 "TP_SMD" TP_1.0_SMD 47.8,27.6 r270 bottom
TP154 "TP_SMD" TP_1.0_SMD 101.9,14.5 r270 bottom
TP156 "TP_SMD" TP_1.0_SMD 15.3,4.6 r180 bottom
TP157 "TP_SMD" TP_1.0_SMD 81.6,34.625 r270 bottom
TP700 "TP_SMD" TP_1.0_SMD 29.9,34.4 r90 bottom
TP701 "TP_SMD" TP_1.0_SMD 28.6,36 r90 bottom
TP703 "TP_SMD" TP_1.0_SMD 28.9,4.7 r180 bottom
TP704 "TP_SMD" TP_1.0_SMD 18.91,4.43 r90 bottom
TP705 "TP_SMD" TP_1.0_SMD 41.6,36.2 r180 bottom
TP706 "TP_SMD" TP_1.0_SMD 24,48.1 r90 bottom
TP707 "TP_SMD" TP_1.0_SMD 34.2,47.6 r90 bottom
TP708 "TP_SMD" TP_1.0_SMD 48.8,34.8 r90 bottom
TP709 "TP_SMD" TP_1.0_SMD 23.425,2.725 r90 bottom
TP711 "TP_SMD" TP_1.0_SMD 39.7,34.7 r90 bottom
TP712 "TP_SMD" TP_1.0_SMD 39.7,38.8 r90 bottom
TP713 "TP_SMD" TP_1.0_SMD 43.8,36.7 r90 bottom
TP714 "TP_SMD" TP_1.0_SMD 43.2,34.1 r90 bottom
TP715 "TP_SMD" TP_1.0_SMD 23.3,35.4 r180 bottom
TP923 "TP_SMD" TP_1.0_SMD 46.5,34.2 r90 bottom
TP930 "TP_SMD" TP_1.0_SMD 56.5,32.5 r180 bottom
TPJ600 "TP_SMD" TP_1.0_SMD 14.353,32.302 r90 bottom
TPJ606 "TP_SMD" TP_1.0_SMD 97.404,47.202 r90 bottom
TPJ607 "TP_SMD" TP_1.0_SMD 66.653,44.101 r90 bottom
TPJ608 "TP_SMD" TP_1.0_SMD 34.528,20.527 r90 bottom
TPJ611 "TP_SMD" TP_1.0_SMD 10.15,51.3 r180 bottom
TPJ612 "TP_SMD" TP_1.0_SMD 10.15,53.85 r180 bottom
TPJ613 "TP_SMD" TP_1.0_SMD 12.7,53.85 r180 bottom
TPJ614 "TP_SMD" TP_1.0_SMD 7.55,49.8 r180 bottom
TPJ650 "TP_SMD" TP_1.0_SMD 108.25,43.248 r90 bottom
TPJ651 "TP_SMD" TP_1.0_SMD 108.25,39.7 r90 bottom
TPJ652 "TP_SMD" TP_1.0_SMD 61.303,16.102 r90 bottom
TPJ653 "TP_SMD" TP_1.0_SMD 51.953,16.102 r90 bottom
TPJ811 "TP_SMD" TP_1.0_SMD 77.9,52.7 r180 bottom
TPJ812 "TP_SMD" TP_1.0_SMD 81.65,53.45 r180 bottom
TPJ814 "TP_SMD" TP_1.0_SMD 84.35,54.3 r180 bottom
TPJ817 "TP_SMD" TP_1.0_SMD 102.65,48.35 r180 bottom
TPJ818 "TP_SMD" TP_1.0_SMD 71.55,40.95 r180 bottom
TPJ820 "TP_SMD" TP_1.0_SMD 80.2,50.95 r180 bottom
TPJ900 "TP_SMD" TP_1.0_SMD 41.602,37.9 r90 bottom
TPJ901 "TP_SMD" TP_1.0_SMD 44.053,38.55 r90 bottom
TPJ902 "TP_SMD" TP_1.0_SMD 24.6,41.4 r180 bottom
TPJ908 "TP_SMD" TP_1.0_SMD 43.952,45.601 r90 bottom
TPJ909 "TP_SMD" TP_1.0_SMD 42.651,43.427 r90 bottom
TPJ910 "TP_SMD" TP_1.0_SMD 48.003,29.65 r90 bottom
TPJ911 "TP_SMD" TP_1.0_SMD 45.453,28.85 r90 bottom
TPJ912 "TP_SMD" TP_1.0_SMD 50.751,34.225 r90 bottom
TPJ913 "TP_SMD" TP_1.0_SMD 50.751,30.501 r90 bottom
TPJ950 "TP_SMD" TP_1.0_SMD 24.452,17.1 r90 bottom
TPJ953 "TP_SMD" TP_1.0_SMD 42.001,25.251 r90 bottom
TPJ954 "TP_SMD" TP_1.0_SMD 43.253,27.501 r90 bottom
TPJ955 "TP_SMD" TP_1.0_SMD 44.503,25.251 r90 bottom
TPJ956 "TP_SMD" TP_1.0_SMD 52.753,39.251 r90 bottom
TPJ957 "TP_SMD" TP_1.0_SMD 51.799,27.599 r180 bottom
TPJ958 "TP_SMD" TP_1.0_SMD 53.15,25.45 r180 bottom
TPJ959 "TP_SMD" TP_1.0_SMD 54.499,27.599 r90 bottom
TPJ960 "TP_SMD" TP_1.0_SMD 53.899,32.598 r90 bottom
TPJ961 "TP_SMD" TP_1.0_SMD 53.95,30.05 r180 bottom
U1 "EFM8BB22F16G-C-QFN28" QFN28_SI_EFM8 86.6,35 r0 top
U100 "TS3A44159" UQFN16_M040_1.8X2.6_TI_RSV 40.39,30.175 r0 top
U600 "LP3982ILD-ADJ" WSON8_M050_3.0X2.5_EP_TI_NGM 18.432,55.147 r0 top
U603 "TLV70536" DSBGA4_M040_0.8X0.8_TI_YFP 44.35,32.45 r180 top
U606 "MCP6001T" SC70-5 26.9,25.675 r270 top
U622 "MCP6001T" SC70-5 67.5,25.7 r180 top
U700 "SIP32431" TDFN4_M050_1.6X1.2_EP_VISH 24.5,33.35 r90 top
U701 "LP3982ILD-ADJ" WSON8_M050_3.0X2.5_EP_TI_NGM 32.125,31.275 r270 top
U702 "TS3A4751" QFN14_M040_2.0X2.0_TI_RUC 42.7,36.675 r180 top
U703 "LTC6102CDD" DFN8_M050_3.0X3.0_EP_LT_DD 28.85,39.9 r180 top
U704 "AD8656" MSOP8_M065_W3.0 27.65,44.6 r0 top
U800 "74LVC4066" DHVQFN14_M050_2.5X3_EP_NXP 70.9,43.6 r270 top
U802 "74LVC4066" DHVQFN14_M050_2.5X3_EP_NXP 70.9,39.1 r270 top
U803 "74LVC1T45" X2-DFN1010-6_M035_DIODES 70.375,47.425 r0 top
U804 "74LVC2G125" DSBGA8_M050_0.9X1.9_TI_YZP 51.575,38.15 r180 top
U805 "TS3A4751" QFN14_M040_2.0X2.0_TI_RUC 64.775,37.07 r90 top
U806 "74LVC4066" DHVQFN14_M050_2.5X3_EP_NXP 70.9,34.6 r270 top
U807 "74LVC1T45" X2-DFN1010-6_M035_DIODES 71.413,26.175 r270 top
U808 "74LVC8T245" VQFN24_M050_3.5X5.5_EP_TI_RHL 63.4,43.05 r0 top
U809 "74LVC2G125" DSBGA8_M050_0.9X1.9_TI_YZP 52.3,41.675 r180 top
U810 "74LVC4066" DHVQFN14_M050_2.5X3_EP_NXP 70.9,30.1 r270 top
U812 "TS3A4751" QFN14_M040_2.0X2.0_TI_RUC 67.1,30.05 r90 top
U860 "74LVC1T45" X2-DFN1010-6_M035_DIODES 51.95,48 r180 top
U861 "74LVC1T45" X2-DFN1010-6_M035_DIODES 67.6,39.9 r90 top
U862 "74LVC1T45" X2-DFN1010-6_M035_DIODES 62.45,38.2 r90 top
U863 "74LVC1T45" X2-DFN1010-6_M035_DIODES 67.7,33.8 r90 top
U900 "EFM32GG12B410F1024GL120-A" BGA120_M050_7.0X7.0_EFM32GGR 46.6,44.5 r180 top
U901 "M24C02" TDFN8_M050_2.0X3.0_EP 51.895,49.95 r0 top
U902 "MX25R8035F" BGA8_M040_1.24X1.75_WLCSP 53.4,34.3 r0 top
U910 "ADC084S021" VSSOP10_M050_W3.0_TI_DGS 48.425,35.025 r0 top
U950 "TS3A4751" QFN14_M040_2.0X2.0_TI_RUC 53.225,44.9 r270 top
X900 "48 MHz" X_KDS_DSX211SH_2.0X1.65-4 45.7,49.75 r0 top

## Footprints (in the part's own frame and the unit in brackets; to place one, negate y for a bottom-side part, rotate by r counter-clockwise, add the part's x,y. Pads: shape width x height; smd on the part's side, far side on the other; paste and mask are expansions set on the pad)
ADHESIVE_PAD_25.0X4.0 [mm] "Adhesive for Sharp Display"
  Top Layer keep-out region: 0,4 0,0.001 25,0.001 25,4.001 0,4
  silkscreen extent 0,0 25,4, body extent 0,0 25,4, height 0.2
BAT_HOLD_MPD_BK-912_CR2032 [mil] "MPD Battery Holder BK-912 (for CR2032)"
  rrect20% 110x200 smd: 1(-430,0) 1(430,0)
  round 157.48 smd paste-295.67 mask-82.68: 2(0,0)
  body extent -450,-394 450,393, height 171
BGA8_M040_1.24X1.75_WLCSP [mm] "BGA, 8 pin. U100"
  round 0.21 smd mask+0.05: A1(-0.35,0.4) A3(0.35,0.4) B2(0,0.2) C1(-0.35,0) C3(0.35,0) D2(0,-0.2) E1(-0.35,-0.4) E3(0.35,-0.4)
  body extent -0.63,-0.89 0.63,0.88, height 0.52
BGA120_M050_7.0X7.0_EFM32GGR [mm] "BGA, 120 Leads, Body 7.0x7.0mmx1,30mm, Pitch 0.50mm (191111)"
  round 0.2 smd mask+0.04: A1(-3,3) A2(-2.5,3) A3(-2,3) A4(-1.5,3) A5(-1,3) A6(-0.5,3) A7(0,3) A8(0.5,3) A9(1,3) A10(1.5,3) A11(2,3) A12(2.5,3) A13(3,3) B1(-3,2.5) B2(-2.5,2.5) B3(-2,2.5) B4(-1.5,2.5) B5(-1,2.5) B6(-0.5,2.5) B7(0,2.5) B8(0.5,2.5) B9(1,2.5) B10(1.5,2.5) B11(2,2.5) B12(2.5,2.5) B13(3,2.5) C1(-3,2) C2(-2.5,2) C3(-2,2) C4(-1.5,2) C5(-1,2) C6(-0.5,2) C7(0,2) C8(0.5,2) C9(1,2) C10(1.5,2) C11(2,2) C12(2.5,2) C13(3,2) D1(-3,1.5) D2(-2.5,1.5) D3(-2,1.5) D11(2,1.5) D12(2.5,1.5) D13(3,1.5) E1(-3,1) E2(-2.5,1) E3(-2,1) E11(2,1) E12(2.5,1) E13(3,1) F1(-3,0.5) F2(-2.5,0.5) F3(-2,0.5) F11(2,0.5) F12(2.5,0.5) F13(3,0.5) G1(-3,0) G2(-2.5,0) G3(-2,0) G11(2,0) G12(2.5,0) G13(3,0) H1(-3,-0.5) H2(-2.5,-0.5) H3(-2,-0.5) H11(2,-0.5) H12(2.5,-0.5) H13(3,-0.5) J1(-3,-1) J2(-2.5,-1) J3(-2,-1) J11(2,-1) J12(2.5,-1) J13(3,-1) K1(-3,-1.5) K2(-2.5,-1.5) K3(-2,-1.5) K11(2,-1.5) K12(2.5,-1.5) K13(3,-1.5) L1(-3,-2) L2(-2.5,-2) L3(-2,-2) L4(-1.5,-2) L5(-1,-2) L6(-0.5,-2) L7(0,-2) L8(0.5,-2) L9(1,-2) L10(1.5,-2) L11(2,-2) L12(2.5,-2) L13(3,-2) M1(-3,-2.5) M2(-2.5,-2.5) M3(-2,-2.5) M4(-1.5,-2.5) M5(-1,-2.5) M6(-0.5,-2.5) M7(0,-2.5) M8(0.5,-2.5) M9(1,-2.5) M10(1.5,-2.5) M11(2,-2.5) M12(2.5,-2.5) M13(3,-2.5) N1(-3,-3) N2(-2.5,-3) N3(-2,-3) N4(-1.5,-3) N5(-1,-3) N6(-0.5,-3) N7(0,-3) N8(0.5,-3) N9(1,-3) N10(1.5,-3) N11(2,-3) N12(2.5,-3) N13(3,-3)
  body extent -3.5,-3.5 3.5,3.5, height 1.3
C0201 [mm] "Capacitor, 9291, HiDens (170502)"
  rrect25% 0.36x0.32 smd paste-0.015 mask+0.05: 1(-0.275,0) 2(0.275,0)
  Top Layer pour cut-out: -0.075,-0.2 -0.075,0.2 0.075,0.2 0.075,-0.2
  body extent -0.32,-0.13 0.32,0.13, height 0.3
C0402 [mm] "Chip Capacitor, 2-Leads, Body 1.0x0.5mm, IPC High Density (190308)"
  rrect20% 0.5x0.5 smd mask+0.051: 1(-0.5,0) 2(0.5,0)
  Top Layer pour cut-out: -0.225,-0.3 -0.225,0.3 0.225,0.3 0.225,-0.3
  body extent -0.5,-0.25 0.5,0.25, height 0.6
C0603 [mm] "Capacitor, 0603, HiDens (190130)"
  rrect25% 0.8x0.85 smd: 1(-0.7,0) 2(0.7,0)
  Top Layer pour cut-out: -0.275,-0.55 -0.275,0.55 0.275,0.55 0.275,-0.55
  body extent -0.88,-0.48 0.87,0.48, height 0.95
C0805 [mm] "Capacitor, 0805 HiDens (190717)"
  rrect25% 0.95x1.35 smd: 1(-0.8,0) 2(0.8,0)
  body extent -1.1,-0.64 1.1,0.64, height 1.45
CK_DP3T_JS203011SCQN [mm] "Switch, C & K DP3T JS203011SCQN (190314)"
  rrect50% 1.2x2.5 smd: 1(-4,-2.75) 2(-2,-2.75) 3(2,-2.75) 4(4,-2.75) 5(-4,2.75) 6(-2,2.75) 7(2,2.75) 8(4,2.75)
  body extent -6.5,-3.75 6.5,3.75, height 5.22
COIL_0402 [mm] "COIL_0402_L (3D from Wurth) (190308)"
  rrect20% 0.55x0.5 smd mask+0.051: 1(-0.525,0) 2(0.525,0)
  Top Layer pour cut-out: -0.225,-0.3 -0.225,0.3 0.225,0.3 0.225,-0.3
  body extent -0.5,-0.25 0.5,0.25, height 0.5
COIL_WURTH_CBF_0603 [mm] "COIL_WURTH_CBF_0603 (= L0603_0.8_L) (181031)"
  rrect10% 0.67x0.88 smd: 1(-0.665,0) 2(0.665,0)
  body extent -0.87,-0.48 0.87,0.48, height 0.95
DFN8_M050_3.0X3.0_EP_LT_DD [mm] "DFN 8 Lead, Pitch 0.5, 3.0x3.0x0.75 Exposed Pad, Linear Tech (171004)"
  rrect50% 0.7x0.25 smd paste-0.025 mask+0.07: 1(-1.4,0.75) 2(-1.4,0.25) 3(-1.4,-0.25) 4(-1.4,-0.75) 5(1.4,-0.75) 6(1.4,-0.25) 7(1.4,0.25) 8(1.4,0.75)
  rect 1x1.8 smd paste-1 mask+0: 9(0,0)
  Top Layer region: 0.825,1.2 -0.693,1.2 -0.825,1.095 -0.825,-1.2 0.825,-1.2
  body extent -1.56,-1.55 1.56,1.55, height 0.8
DFN2111-7_M050_1.2X2.1_NXP [mm] "DFN2111-7 NXP Pitch 035 1.2x2.1x0.5, NXP (190312)"
  rrect20% 0.53x0.19 smd mask+0.05: 1(-0.415,0.75) 2(-0.415,0.25) 3(-0.415,-0.25) 4(-0.415,-0.75) 5(0.415,-0.5) 6(0.415,0) 7(0.415,0.5)
  body extent -0.6,-1.05 0.6,1.05, height 0.51
DHVQFN14_M050_2.5X3_EP_NXP [mm] "DHVQFN, 14 Leads, 2.5x3.0x0.85, Pitch 0.50, Thermal Pad 1.0x1.5 (190314)"
  oval 0.3x0.7 smd: 1(-0.25,1.45) 7(-0.25,-1.45) 8(0.25,-1.45) 14(0.25,1.45)
  oval 0.7x0.3 smd: 2(-1.2,1) 3(-1.2,0.5) 4(-1.2,0) 5(-1.2,-0.5) 6(-1.2,-1) 9(1.2,-1) 10(1.2,-0.5) 11(1.2,0) 12(1.2,0.5) 13(1.2,1)
  rrect10% 1x1.5 smd: 17(0,0)
  body extent -1.25,-1.5 1.25,1.5, height 1.1
DSBGA4_M040_0.8X0.8_TI_YFP [mm] "DS-BGA, 4 Leads, Body 0.8x0.8 H:0.5, Pitch 0.40"
  round 0.23 smd mask+0.04: A1(-0.2,0.2) A2(0.2,0.2) B1(-0.2,-0.2) B2(0.2,-0.2)
  body extent -0.4,-0.4 0.4,0.4, height 0.51
DSBGA8_M050_0.9X1.9_TI_YZP [mm] "DS-BGA, 8 Leads, Body 0.9x1.9 H:0.5, Pitch 0.50"
  round 0.23 smd: A1(-0.25,0.75) A2(0.25,0.75) B1(-0.25,0.25) B2(0.25,0.25) C1(-0.25,-0.25) C2(0.25,-0.25) D1(-0.25,-0.75) D2(0.25,-0.75)
  body extent -0.45,-0.95 0.45,0.95, height 0.51
FCI_10137065_USB-C_RCPT_A1 [mm] "FCI AMPHENOL 10137065 USB-C Receptacle (Slot PinInPaste) (180404), extra paste added for solder leg to form proper fillet"
  oval 1.8x3.1 hole 0.7 slot 2 at 90 deg: 25(-4.32,-3.05)
  oval 1.3x2.6 on Top Paste: 25(-4.32,-3.05) 26(4.32,-3.05)
  oval 1.8x3.1 hole 0.7 slot 2 at 90 deg paste+0: 26(4.32,-3.05)
  oval 1.2x2.489 on Top Paste: 27(-4.32,2)
  oval 1.2x2.5 hole 0.6 slot 1.9 at 90 deg paste+0: 27(-4.32,2)
  oval 1.638x1.194 on Top Paste: 27(-4.025,1.35)
  oval 1.647x1.2 hole 0.6 slot 1.247 at 0 deg: 27(-4.025,1.35)
  oval 1.847x1.2 hole 0.6 slot 1.247 at 0 deg: 28(4.025,1.35)
  oval 1.841x1.194 on Top Paste: 28(4.025,1.35)
  oval 1.2x2.5 hole 0.6 slot 1.9 at 90 deg: 28(4.32,2)
  oval 1.194x2.489 on Top Paste: 28(4.32,2)
  rrect20% 0.27x0.9 smd mask+0.076: A1(-2.625,2.7) A2(-2.125,2.7) A3(-1.625,2.7) A4(-1.125,2.7) A5(-0.625,2.7) A6(-0.125,2.7) A7(0.375,2.7) A8(0.875,2.7) A9(1.375,2.7) A10(1.875,2.7) A11(2.375,2.7) A12(2.875,2.7)
  rrect20% 0.27x0.8 smd mask+0.076: B1(2.625,1.1) B2(2.125,1.1) B3(1.625,1.1) B4(1.125,1.1) B5(0.625,1.1) B6(0.125,1.1) B7(-0.375,1.1) B8(-0.875,1.1) B9(-1.375,1.1) B10(-1.875,1.1) B11(-2.375,1.1) B12(-2.875,1.1)
  round 0 hole 0.6 unplated mask+0.102: M1(-3.6,0)
  round 0 hole 0.5 slot 0.85 at 0 deg unplated mask+0.102: M2(3.6,0)
  Top Layer region: 3.42,1.35 3.42,3.606 3.466,3.836 3.596,4.031 3.79,4.161 4.02,4.206 4.02,4.206 4.62,4.206 4.85,4.161 5.044,4.031 5.174,3.836 5.22,3.606 5.22,3.606 5.22,1.35 5.174,1.12 5.044,0.926 4.85,0.796 4.62,0.75 4.62,0.75 4.02,0.75 3.79,0.796 3.596,0.926 3.466,1.12 3.42,1.35
  Top Layer region: -5.22,1.35 -5.22,3.606 -5.174,3.836 -5.044,4.031 -4.85,4.161 -4.62,4.206 -4.62,4.206 -4.02,4.206 -3.79,4.161 -3.596,4.031 -3.466,3.836 -3.42,3.606 -3.42,3.606 -3.42,1.35 -3.466,1.12 -3.596,0.926 -3.79,0.796 -4.02,0.75 -4.02,0.75 -4.62,0.75 -4.85,0.796 -5.044,0.926 -5.174,1.12 -5.22,1.35
  Top Layer keep-out region: -3.9,-4.85 3.9,-4.85 3.9,0.4 -3.9,0.4
  body extent -4.47,-5.3 4.47,2.85, height 3.14
HDR_M254-1X2 [mm] "Connector; Header; 2 Position (170508)"
  round 1.6 hole 1: 1(0,0) 2(2.54,0)
  body extent -1.07,-1.17 3.61,1.17, height 8.12
HDR_M254-1X3_NO_3D [mm] "No 3D model for this component"
  round 1.6 hole 1: 1(0,0) 2(2.54,0) 3(5.08,0)
HDR_M254-1X16_NO_3D [mm] "No 3D model for this component (200325)"
  round 1.5 hole 0.9: 1(0,0) 2(2.54,0) 3(5.08,0) 4(7.62,0) 5(10.16,0) 6(12.7,0) 7(15.24,0) 8(17.78,0) 9(20.32,0) 10(22.86,0) 11(25.4,0) 12(27.94,0) 13(30.48,0) 14(33.02,0) 15(35.56,0) 16(38.1,0)
HDR_SULLINS_M127_PEG-2X10 [mil] "Sullins, GRPB102VQS (180319)"
  rrect50% 30x87 smd: 1(-25,-72.5) 2(-25,72.5) 3(25,-72.5) 4(25,72.5) 5(75,-72.5) 6(75,72.5) 7(125,-72.5) 8(125,72.5) 9(175,-72.5) 10(175,72.5) 11(225,-72.5) 12(225,72.5) 13(275,-72.5) 14(275,72.5) 15(325,-72.5) 16(325,72.5) 17(375,-72.5) 18(375,72.5) 19(425,-72.5) 20(425,72.5)
  round 0 hole 39.37 unplated mask+3.94: M1(0,0) M2(400,0)
  body extent -50,-100 450,101, height 197
HOLE_3.0_5.0_PL [mm] "Hole 3.0 mm, Plated (171122)"
  round 5 hole 3: 1(0,0)
HOLE_3.0_NPL [mm] "HOLE_3.0_NPL (170815)"
  round 0 hole 3 unplated mask+0.2: 1(0,0)
  body extent -1.5,-1.5 1.5,1.5
HRS_U.FL-R-SMT [mm] "COAX_HIROSE_U.FL_CL331-0471 (170228)"
  rrect20% 1.05x1.1 smd mask+0.051: 1(0,-1.6)
  rrect20% 1.05x2.25 smd mask+0.051: 2(1.5,0) 3(-1.5,0)
  Top Layer pour cut-out: 0.85,-0.9 -0.85,-0.9 -0.85,-0.9 -0.85,1.2 0.85,1.2 0.85,1.2
  body extent -1.3,-1.3 1.3,1.55, height 0.9
KLS_KLS1-242D_FPC_0.5-10 [mm] "KLS1-242D-1.2-10 (3D IS FROM MOL 5450) (201021)"
  rrect50% 0.3x1.25 smd mask+0.076: 1(0,0) 2(0.5,0) 3(1,0) 4(1.5,0) 5(2,0) 6(2.5,0) 7(3,0) 8(3.5,0) 9(4,0) 10(4.5,0)
  rrect5% 2x2.45 smd: 11(-1.69,-2.6) 12(6.19,-2.6)
  body extent -2.85,-5.05 7.35,-0.05, height 1.2
LABEL_4CORNERS_19.0X6.0 [mm]
  silkscreen extent -9.5,-3 9.5,3
LABEL_P101_PIN_TABLE_SL [mm]
  silkscreen extent -2.4,-12.5 2.4,12.5
LED_0402 [mm] "Chip Diode, 2-Leads, Body 1.00x0.50mm, IPC High Density (170127)"
  rrect10% 0.45x0.6 smd: 1(-0.45,0) 2(0.45,0)
  body extent -0.55,-0.33 0.55,0.33, height 0.25
LED_0402_CAT2 [mm] "(200921)"
  rrect10% 0.45x0.6 smd: 1(-0.45,0) 2(0.45,0)
  body extent -0.55,-0.33 0.55,0.33, height 0.25
LED_AVAGO_HSMF-C165-4 [mm] "LED (dual) Avago HSMF-C165 Grn+Red 1.6x0.8x0.5 (200226)"
  rrect20% 0.7x0.4 smd: 1(-0.65,-0.35) 2(-0.65,0.35) 3(0.65,0.35) 4(0.65,-0.35)
  body extent -0.8,-0.4 0.8,0.4, height 0.52
LED_LUMEX_SML-LX0404-4 [mm] "LED, LUMEX, SML LX0404 1.0x1.0x0.25 NB! Pin numbering (180111)"
  rrect25% 0.45x0.45 smd mask+0.05: 1(-0.425,-0.425) 2(-0.425,0.425) 3(0.425,0.425) 4(0.425,-0.425)
  body extent -0.5,-0.5 0.5,0.5, height 0.31
LOGO_BEE_H7.0 [mm] "Silicon Labs Logo Bee (210415)"
  silkscreen extent -3.58,0 3.61,6.92
LOGO_SEGGER_10.0X5.0_SM [mm] "Logo, Segger 10.0x5.0, Top Solder + M19 + Top Overlay"
LOGO_SILABS_W14.0_SILK [mm] "LOGO_SILABS_W14.0 SILKSCREEN ONLY"
  silkscreen extent 0.03,0 13.99,6.83
LOGO_SILABS_W18.0 [mm]
  silkscreen extent 0.02,0.02 16.98,8.32
MSOP8_M065_W3.0 [mm] "MSOP, 8-Leads, Body 3.0x3.0mm, Pitch 0.65mm (170921)"
  rrect20% 0.889x0.42 smd mask+0.048: 1(-2.105,0.975) 2(-2.105,0.325) 3(-2.105,-0.325) 4(-2.105,-0.975) 5(2.106,-0.975) 6(2.106,-0.325) 7(2.106,0.325) 8(2.106,0.975)
  body extent -1.55,-1.55 1.55,1.55, height 1.11
OLED_LS013B7DH03 [mm] "LS013B7DH03 (200526)"
  body extent -13.3,-18.6 13.3,13.23, height 3.8
QFN14_M040_2.0X2.0_TI_RUC [mm] "QFN 14 Leads, Pitch 0.4 mm, 2.0 x 2.0 H: 0.37, TI: RUC (180613)"
  rrect20% 0.68x0.2 smd: 1(-0.885,0.8) 2(-0.885,0.4) 3(-0.885,0) 4(-0.885,-0.4) 5(-0.885,-0.8) 8(0.885,-0.8) 9(0.885,-0.4) 10(0.885,0) 11(0.885,0.4) 12(0.885,0.8)
  rrect20% 0.2x0.68 smd: 6(-0.2,-0.885) 7(0.2,-0.885) 13(0.2,0.885) 14(-0.2,0.885)
  body extent -1,-1 1,1, height 0.41
QFN28_SI_EFM8 [mm] "QFN, 28-Leads, Body 5.00x5.00mm, Pitch 0.50mm, Thermal Pad 3.25x3.25mm, IPC High Density"
  rect 0.95x0.3 smd mask+0.05: 1(-2.4,1.5) 2(-2.4,1) 3(-2.4,0.5) 4(-2.4,0) 5(-2.4,-0.5) 6(-2.4,-1) 7(-2.4,-1.5) 15(2.4,-1.5) 16(2.4,-1) 17(2.4,-0.5) 18(2.4,0) 19(2.4,0.5) 20(2.4,1) 21(2.4,1.5)
  rect 0.3x0.95 smd mask+0.05: 8(-1.5,-2.4) 9(-1,-2.4) 10(-0.5,-2.4) 11(0,-2.4) 12(0.5,-2.4) 13(1,-2.4) 14(1.5,-2.4)
  rect 0.35x0.95 smd mask+0.05: 22(1.5,2.4) 23(1,2.4) 24(0.5,2.4) 25(0,2.4) 26(-0.5,2.4) 27(-1,2.4) 28(-1.5,2.4)
  rect 3.35x3.35 smd mask+0.05: 29(0,0)
  body extent -2.5,-2.5 2.5,2.5, height 0.8
R0201 [mm] "Resistor (Chip2PinSM127P600-8N) (170921)"
  rrect25% 0.34x0.32 smd: 1(-0.3,0) 2(0.3,0)
  Top Layer pour cut-out: -0.1,-0.2 -0.1,0.2 0.1,0.2 0.1,-0.2
  body extent -0.32,-0.13 0.32,0.13, height 0.3
R0402 [mm] "Chip Resistor, 2-Leads, Body 1.0x0.5mm, HiDens (190308)"
  rrect20% 0.6x0.6 smd mask+0.051: 1(-0.45,0) 2(0.45,0)
  Top Layer pour cut-out: -0.125,-0.3 -0.125,0.3 0.125,0.3 0.125,-0.3
  body extent -0.5,-0.25 0.5,0.25, height 0.6
R0603 [mm] "Chip Resistor, 0603, HiDens (190130)"
  rrect25% 0.85x0.9 smd: 1(-0.7,0) 2(0.7,0)
  Top Layer pour cut-out: -0.25,-0.575 -0.25,0.575 0.25,0.575 0.25,-0.575
  body extent -0.88,-0.48 0.87,0.48, height 0.95
R1206 [mm] "Resistor, 1206, HiDens (191114)"
  rrect25% 0.85x1.65 smd paste-0.04 mask+0.07: 1(-1.425,0) 2(1.425,0)
  body extent -1.6,-0.8 1.6,0.8, height 1
RES_MNR04-8 [mm] "Resistor Array, ROHM MNR04 8-Pin 2.0x1.0x0.35 (!80615)"
  rrect20% 0.4x0.5 smd: 1(-0.75,-0.45) 4(0.75,-0.45) 5(0.75,0.45) 8(-0.75,0.45)
  rrect20% 0.3x0.5 smd: 2(-0.25,-0.45) 3(0.25,-0.45) 6(0.25,0.45) 7(-0.25,0.45)
  body extent -1,-0.4 1,0.4, height 0.5
SC70-5 [mm] "SC70-5 = SOT353, HiDens (170511)"
  rrect25% 0.6x0.4 smd paste-0.03 mask+0.05: 1(-0.95,0.65) 2(-0.95,0) 3(-0.95,-0.65) 4(0.95,-0.65) 5(0.95,0.65)
  body extent -1.12,-0.97 1.16,1.03, height 0.95
SOT563 [mm] "SOT563 (_M050_W1.2_), 6-Leads, Body 1.60x1.20, Pitch 0.5, HiDens (170926)"
  rrect25% 0.6x0.3 smd: 1(-0.65,0.5) 2(-0.65,0) 3(-0.65,-0.5) 4(0.65,-0.5) 5(0.65,0) 6(0.65,0.5)
  body extent -0.65,-0.85 0.65,0.85, height 0.6
SOT563_DIODES [mm] "SOT563 (_M050_W1.2_), 6-Leads, Body 1.60x1.20, Pitch 0.5, HiDens (170926)"
  rrect25% 0.5x0.375 smd: 1(-0.85,0.5) 2(-0.85,0) 3(-0.85,-0.5) 4(0.85,-0.5) 5(0.85,0) 6(0.85,0.5)
  body extent -0.66,-0.85 0.65,0.85, height 0.6
SW_ALPS_SKRHAAE010 [mm] "Switch, ALPS / ALPINE (200615)"
  rrect20% 1.35x1 smd: 1(-3.575,1.425) 2(-3.575,0) 3(-3.575,-1.425) 4(3.575,1.425) 5(3.575,0) 6(3.575,-1.425)
  rrect20% 2x1.8 smd: 7(0,4.05) 8(0,-4.05)
  round 0 hole 0.75 mask+0.102: M1(0,1.9)
  round 0 hole 1.05 mask+0.102: M2(0,-1.9)
  body extent -3.74,-3.75 3.74,3.75, height 5
SW_CK_PTS810_SJM_250 [mm] "Switch C&K PTS810_SJM_250 (grey button) (180319)"
  rrect20% 1.05x0.65 smd: 1(-2.075,1.075) 2(2.075,1.075) 3(-2.075,-1.075) 4(2.075,-1.075)
  body extent -2.29,-1.6 2.29,1.6, height 2.5
TDFN4_M050_1.6X1.2_EP_VISH [mm] "TDFN, 4-Leads, Body 1.60x1.20mm, IPC HiDens (180111)"
  rrect10% 0.55x0.3 smd: 1(-0.725,0.25) 2(-0.725,-0.25) 3(0.725,-0.25) 4(0.725,0.25)
  rrect10% 0.5x0.86 smd paste-0.05: 5(0,0)
  body extent -0.8,-0.6 0.8,0.6, height 0.61
TDFN8_M050_2.0X3.0_EP [mm] "TDFN8_M050_2.0x3.0_EP (170921)"
  rrect20% 0.75x0.3 smd: 1(-1.45,0.75) 2(-1.45,0.25) 3(-1.45,-0.25) 4(-1.45,-0.75) 5(1.45,-0.75) 6(1.45,-0.25) 7(1.45,0.25) 8(1.45,0.75)
  rrect10% 1.5x1.4 smd: 9(0,0)
  body extent -1.5,-1 1.5,1, height 1.01
TP_1.0_SMD [mm] "Test Point, 1.0 mm, SMD (170509)"
  round 1 smd paste-0.501: 1(0,0)
  body extent -0.5,-0.5 0.5,0.5, height 0.04
UQFN16_M040_1.8X2.6_TI_RSV [mm] "UQFN 16 Leads, Pitch 0.4, 1.9x2.6x0.5, TI: RSV (190816)"
  rrect20% 0.7x0.2 smd paste+0 mask+0.05: 1(-0.75,0.6)
  rrect20% 0.6x0.2 smd paste+0 mask+0.05: 2(-0.8,0.2) 3(-0.8,-0.2) 4(-0.8,-0.6) 9(0.8,-0.6) 10(0.8,-0.2) 11(0.8,0.2) 12(0.8,0.6)
  rrect20% 0.2x0.6 smd paste+0 mask+0.05: 5(-0.6,-1.2) 6(-0.2,-1.2) 7(0.2,-1.2) 8(0.6,-1.2) 13(0.6,1.2) 14(0.2,1.2) 15(-0.2,1.2) 16(-0.6,1.2)
  body extent -0.9,-1.3 0.9,1.3, height 0.56
VQFN24_M050_3.5X5.5_EP_TI_RHL [mm] "VQFN 24 Leads, Pitch 0.50 3.5x5.0x0.9, TI: RHL (171011)"
  rrect20% 0.28x0.99 smd: 1(-0.75,2.795) 12(-0.75,-2.795) 13(0.75,-2.795) 24(0.75,2.795)
  rrect20% 0.99x0.28 smd: 2(-1.795,2.25) 3(-1.795,1.75) 4(-1.795,1.25) 5(-1.795,0.75) 6(-1.795,0.25) 7(-1.795,-0.25) 8(-1.795,-0.75) 9(-1.795,-1.25) 10(-1.795,-1.75) 11(-1.795,-2.25) 14(1.795,-2.25) 15(1.795,-1.75) 16(1.795,-1.25) 17(1.795,-0.75) 18(1.795,-0.25) 19(1.795,0.25) 20(1.795,0.75) 21(1.795,1.25) 22(1.795,1.75) 23(1.795,2.25)
  rrect5% 2.05x4.05 smd: 25(0,0)
  Top Layer region: 0.39,-3.26 0.39,-2 -0.39,-2 -0.39,-3.26 -0.39,-3.266 -0.385,-3.277 -0.377,-3.285 -0.366,-3.29 -0.36,-3.29 -0.36,-3.29 -0.14,-3.29 -0.134,-3.29 -0.123,-3.285 -0.115,-3.277 -0.11,-3.266 -0.11,-3.26 -0.11,-3.26 -0.11,-2.32 -0.11,-2.316 -0.107,-2.309 -0.101,-2.303 -0.094,-2.3 -0.09,-2.3 -0.09,-2.3 0.09,-2.3 0.094,-2.3 0.101,-2.303 0.107,-2.309 0.11,-2.316 0.11,-2.32 0.11,-2.32 0.11,-3.26 0.11,-3.266 0.115,-3.277 0.123,-3.285 0.134,-3.29 0.14,-3.29 0.14,-3.29 0.36,-3.29 0.366,-3.29 0.377,-3.285 0.385,-3.277 0.39,-3.266 0.39,-3.26
  Top Layer region: -0.39,3.26 -0.39,2 0.39,2 0.39,3.26 0.39,3.266 0.385,3.277 0.377,3.285 0.366,3.29 0.36,3.29 0.36,3.29 0.14,3.29 0.134,3.29 0.123,3.285 0.115,3.277 0.11,3.266 0.11,3.26 0.11,3.26 0.11,2.32 0.11,2.316 0.107,2.309 0.101,2.303 0.094,2.3 0.09,2.3 0.09,2.3 -0.09,2.3 -0.094,2.3 -0.101,2.303 -0.107,2.309 -0.11,2.316 -0.11,2.32 -0.11,2.32 -0.11,3.26 -0.11,3.266 -0.115,3.277 -0.123,3.285 -0.134,3.29 -0.14,3.29 -0.14,3.29 -0.36,3.29 -0.366,3.29 -0.377,3.285 -0.385,3.277 -0.39,3.266 -0.39,3.26
  body extent -1.75,-2.75 1.75,2.75, height 1
VSSOP10_M050_W3.0_TI_DGS [mm] "VSSOP, 10-Leads, 3.0x3.0x(max1.1), Pitch 0.50mm, (TI: DGS) (190816)"
  rrect20% 1.45x0.3 smd: 1(-2.2,1) 2(-2.2,0.5) 3(-2.2,0) 4(-2.2,-0.5) 5(-2.2,-1) 6(2.2,-1) 7(2.2,-0.5) 8(2.2,0) 9(2.2,0.5) 10(2.2,1)
  body extent -1.5,-1.5 1.5,1.5, height 1.1
WCON_1125B-1210_HOR_PEG-2X10 [mm] "WCON 2x10 header (201021)"
  rrect50% 1.27x3.175 smd: 1(-1.27,4.24) 2(-1.27,8.43) 3(1.27,4.24) 4(1.27,8.43) 5(3.81,4.24) 6(3.81,8.43) 7(6.35,4.24) 8(6.35,8.43) 9(8.89,4.24) 10(8.89,8.43) 11(11.43,4.24) 12(11.43,8.43) 13(13.97,4.24) 14(13.97,8.43) 15(16.51,4.24) 16(16.51,8.43) 17(19.05,4.24) 18(19.05,8.43) 19(21.59,4.24) 20(21.59,8.43)
  round 0 hole 1.9 unplated paste+0.91 mask+0.1: M1(0,0) M2(20.32,0)
  body extent -2.54,-7.11 22.86,9.15, height 6.1
WCON_3132_HDR_M127_SMD-2X10 [mm] "WCON_3132_HDR_M127_SMD-2X10 (210215)"
  rrect50% 0.74x2.4 smd: 1(-5.715,-1.95) 2(-5.715,1.95) 3(-4.445,-1.95) 4(-4.445,1.95) 5(-3.175,-1.95) 6(-3.175,1.95) 7(-1.905,-1.95) 8(-1.905,1.95) 9(-0.635,-1.95) 10(-0.635,1.95) 11(0.635,-1.95) 12(0.635,1.95) 13(1.905,-1.95) 14(1.905,1.95) 15(3.175,-1.95) 16(3.175,1.95) 17(4.445,-1.95) 18(4.445,1.95) 19(5.715,-1.95) 20(5.715,1.95)
  body extent -6.35,-4.53 6.35,2.84, height 6.58
WSON8_M050_3.0X2.5_EP_TI_NGM [mm] "WSON8, Pitch 0.5, 3.0x2.5x0.8 EP TI: NGM (181205)"
  rrect20% 0.5x0.25 smd mask+0.051: 1(-1.15,0.75) 2(-1.15,0.25) 3(-1.15,-0.25) 4(-1.15,-0.75) 5(1.15,-0.75) 6(1.15,-0.25) 7(1.15,0.25) 8(1.15,0.75)
  rrect10% 1.2x1.5 smd mask+0.051: 9(0,0)
  body extent -1.5,-1.25 1.5,1.25, height 0.8
X2-DFN1006-2 [mm] "Diodes case X2-DFN1006-2 part DESD5V0S1BLD (201012)"
  rrect20% 0.4x0.7 smd mask+0.04: 1(-0.35,0) 2(0.35,0)
  body extent -0.5,-0.3 0.5,0.3, height 0.41
X2-DFN1010-6_M035_DIODES [mm] "X2-DFN1010-6 Pitch 0.35 1.0x1.0x0.4, Diodes Inc (181025)"
  rrect20% 0.55x0.2 smd mask+0.04: 1(-0.35,0.35) 2(-0.35,0) 3(-0.35,-0.35) 4(0.35,-0.35) 5(0.35,0) 6(0.35,0.35)
  body extent -0.5,-0.5 0.5,0.5, height 0.41
X2-DFN2015-3_DIODES [mm] "X2-DFN2015-3 DIODES (181204)"
  rrect10% 0.5x0.31 smd mask+0.07: 1(-0.9,0.5) 2(-0.9,-0.5)
  rrect10% 0.75x0.31 smd mask+0.07: 3(0.775,0)
  Top Layer region: 0.5,0.55 0.5,-0.55 0.5,-0.57 0.485,-0.607 0.457,-0.635 0.42,-0.65 0.4,-0.65 0.4,-0.65 -0.4,-0.65 -0.42,-0.65 -0.457,-0.635 -0.485,-0.607 -0.5,-0.57 -0.5,-0.55 -0.5,-0.55 -0.5,0.55 -0.5,0.57 -0.485,0.607 -0.457,0.635 -0.42,0.65 -0.4,0.65 -0.4,0.65 0.4,0.65 0.42,0.65 0.457,0.635 0.485,0.607 0.5,0.57 0.5,0.55
  body extent -1.04,-0.79 1.04,0.79, height 0.4
X_KDS_DSX211SH_2.0X1.65-4 [mm] "X_KDS_DSX211SH_2.0X1.65-4 (190312)"
  rrect20% 0.9x0.8 smd: 1(-0.7,-0.55) 2(0.7,-0.55) 3(0.7,0.55) 4(-0.7,0.55)
  body extent -1.07,-0.87 1.07,0.87, height 0.5

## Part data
LED900: library part Yellow
LED901: library part Blue

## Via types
v1: diameter 0.508, hole 0.25, Top Layer to Bottom Layer, tented both sides, 1070 vias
